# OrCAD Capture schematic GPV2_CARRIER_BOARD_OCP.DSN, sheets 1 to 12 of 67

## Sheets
1 001 Cover Page: title: Glacier Point V2; rev: 3.02
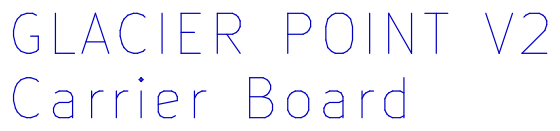
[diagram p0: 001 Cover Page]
2 002 Title Page Index
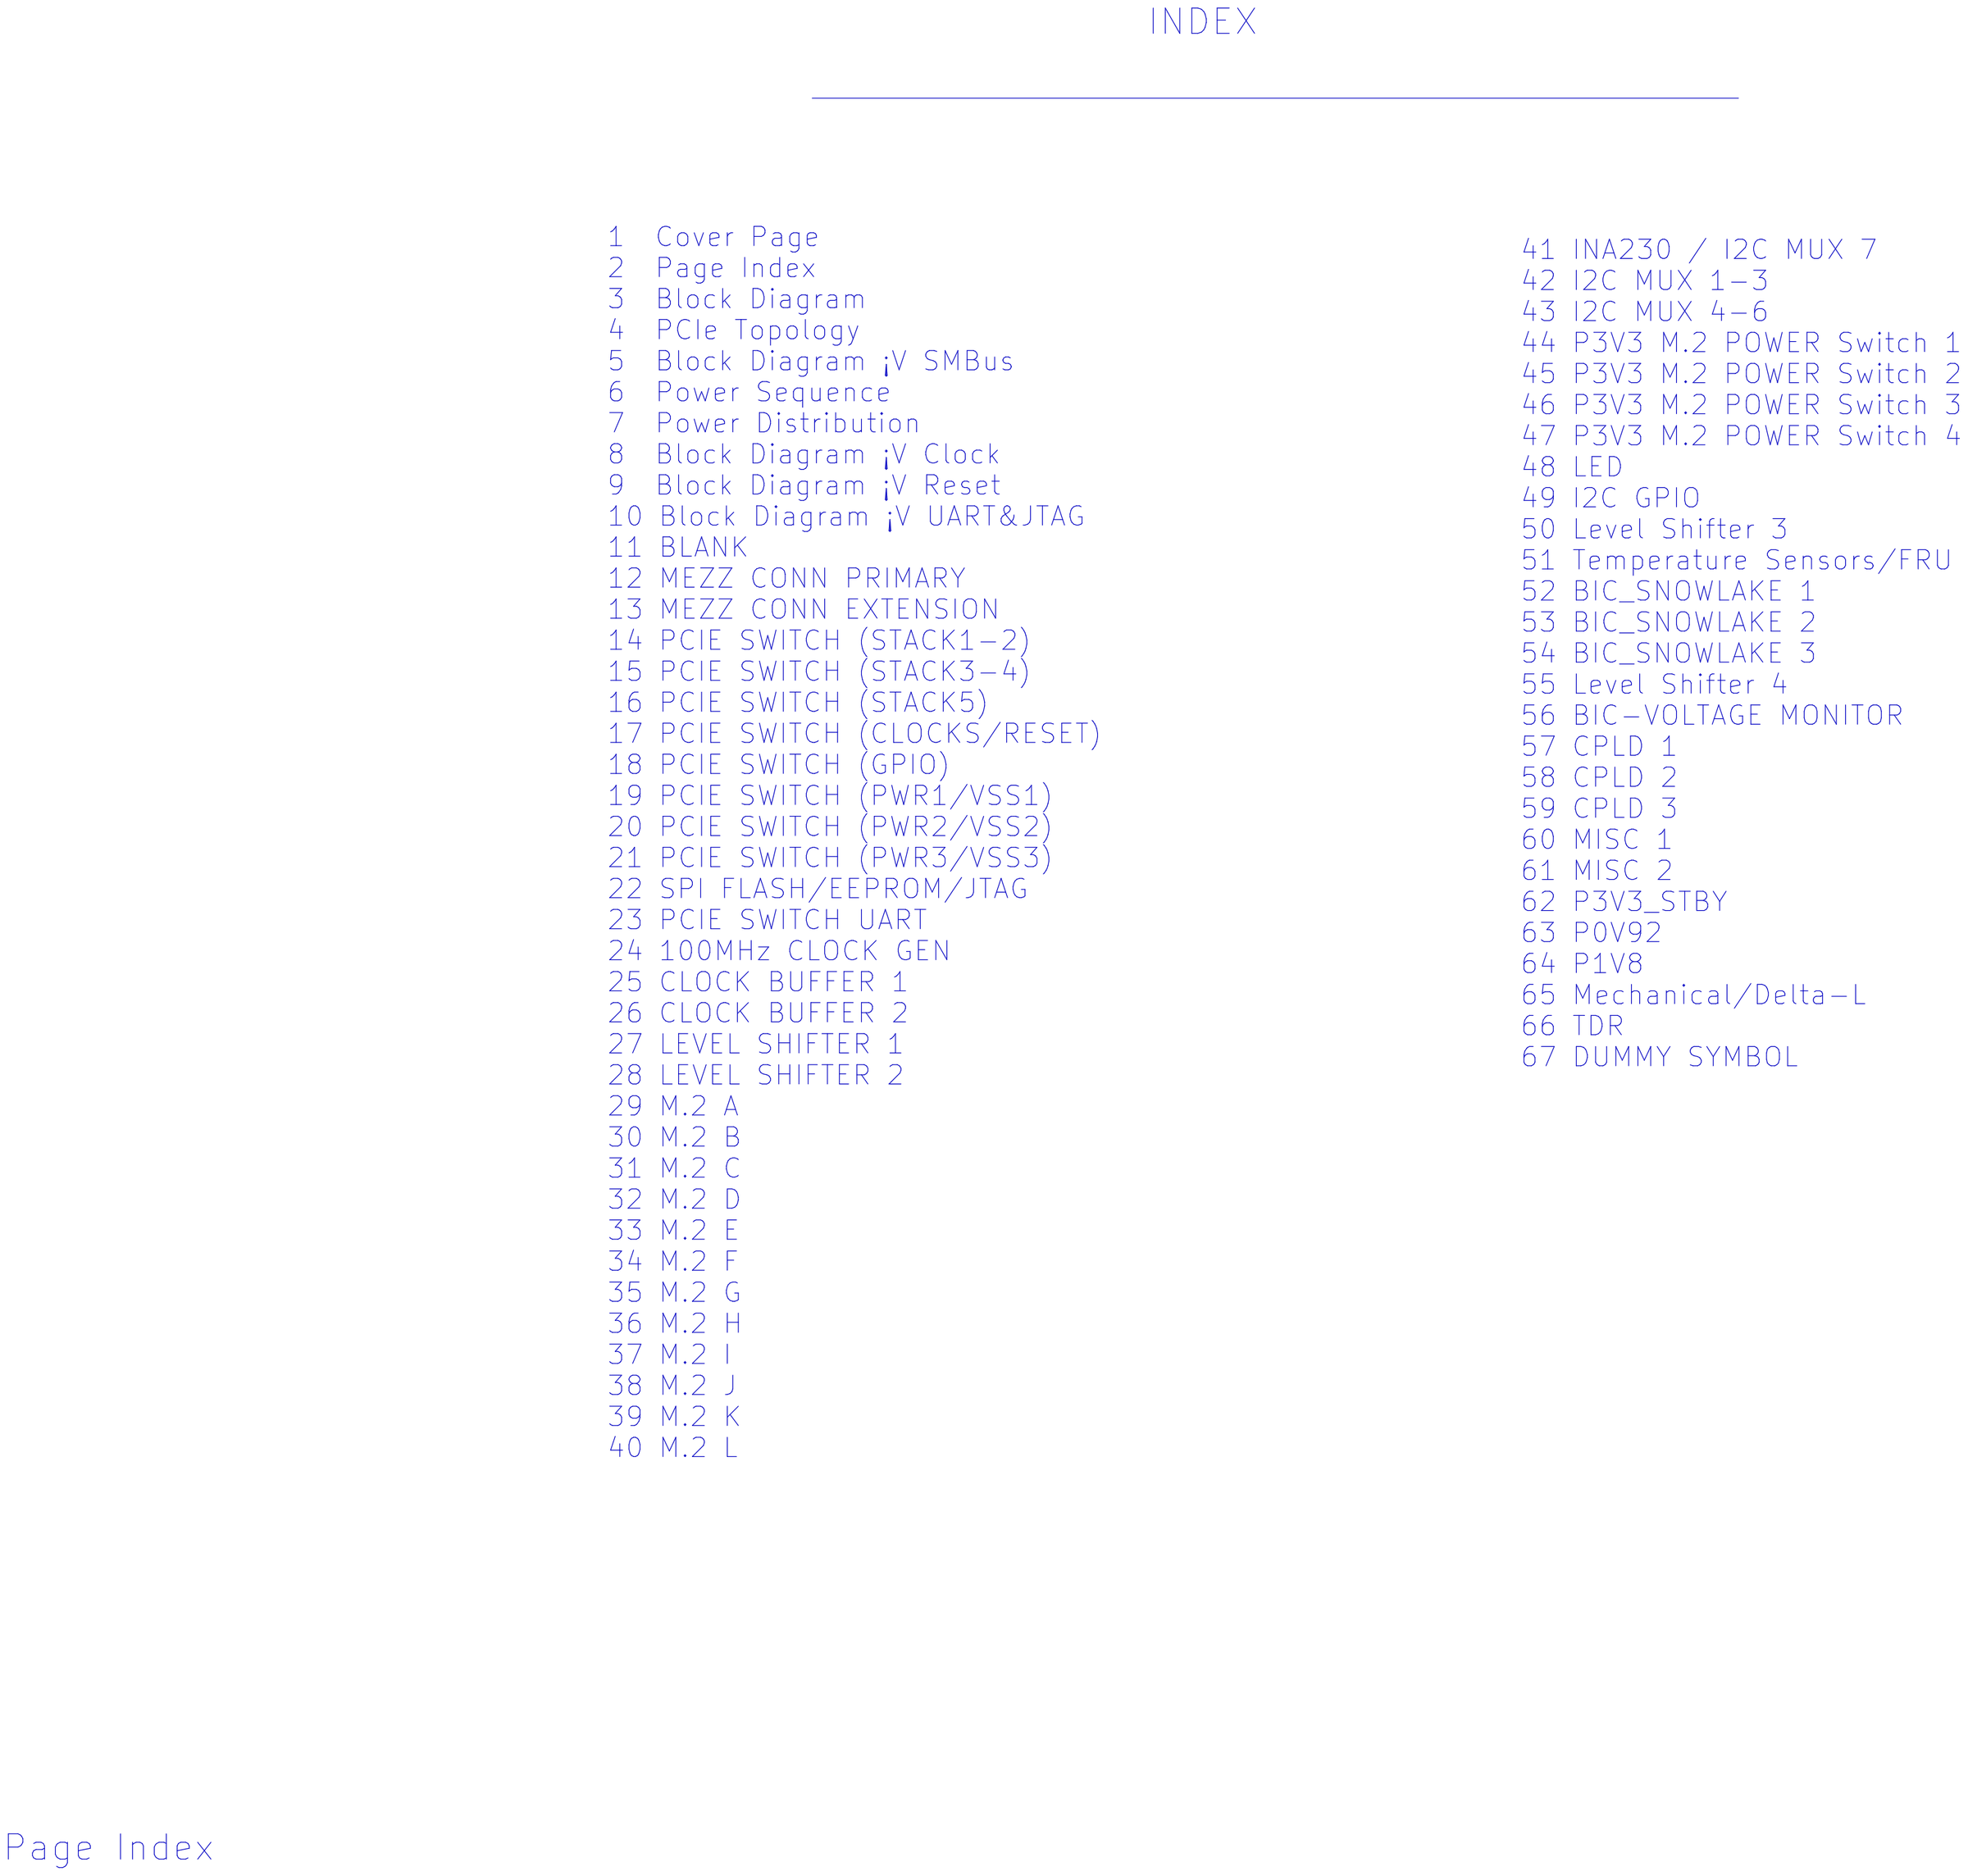
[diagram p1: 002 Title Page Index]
3 003 Block Diagram
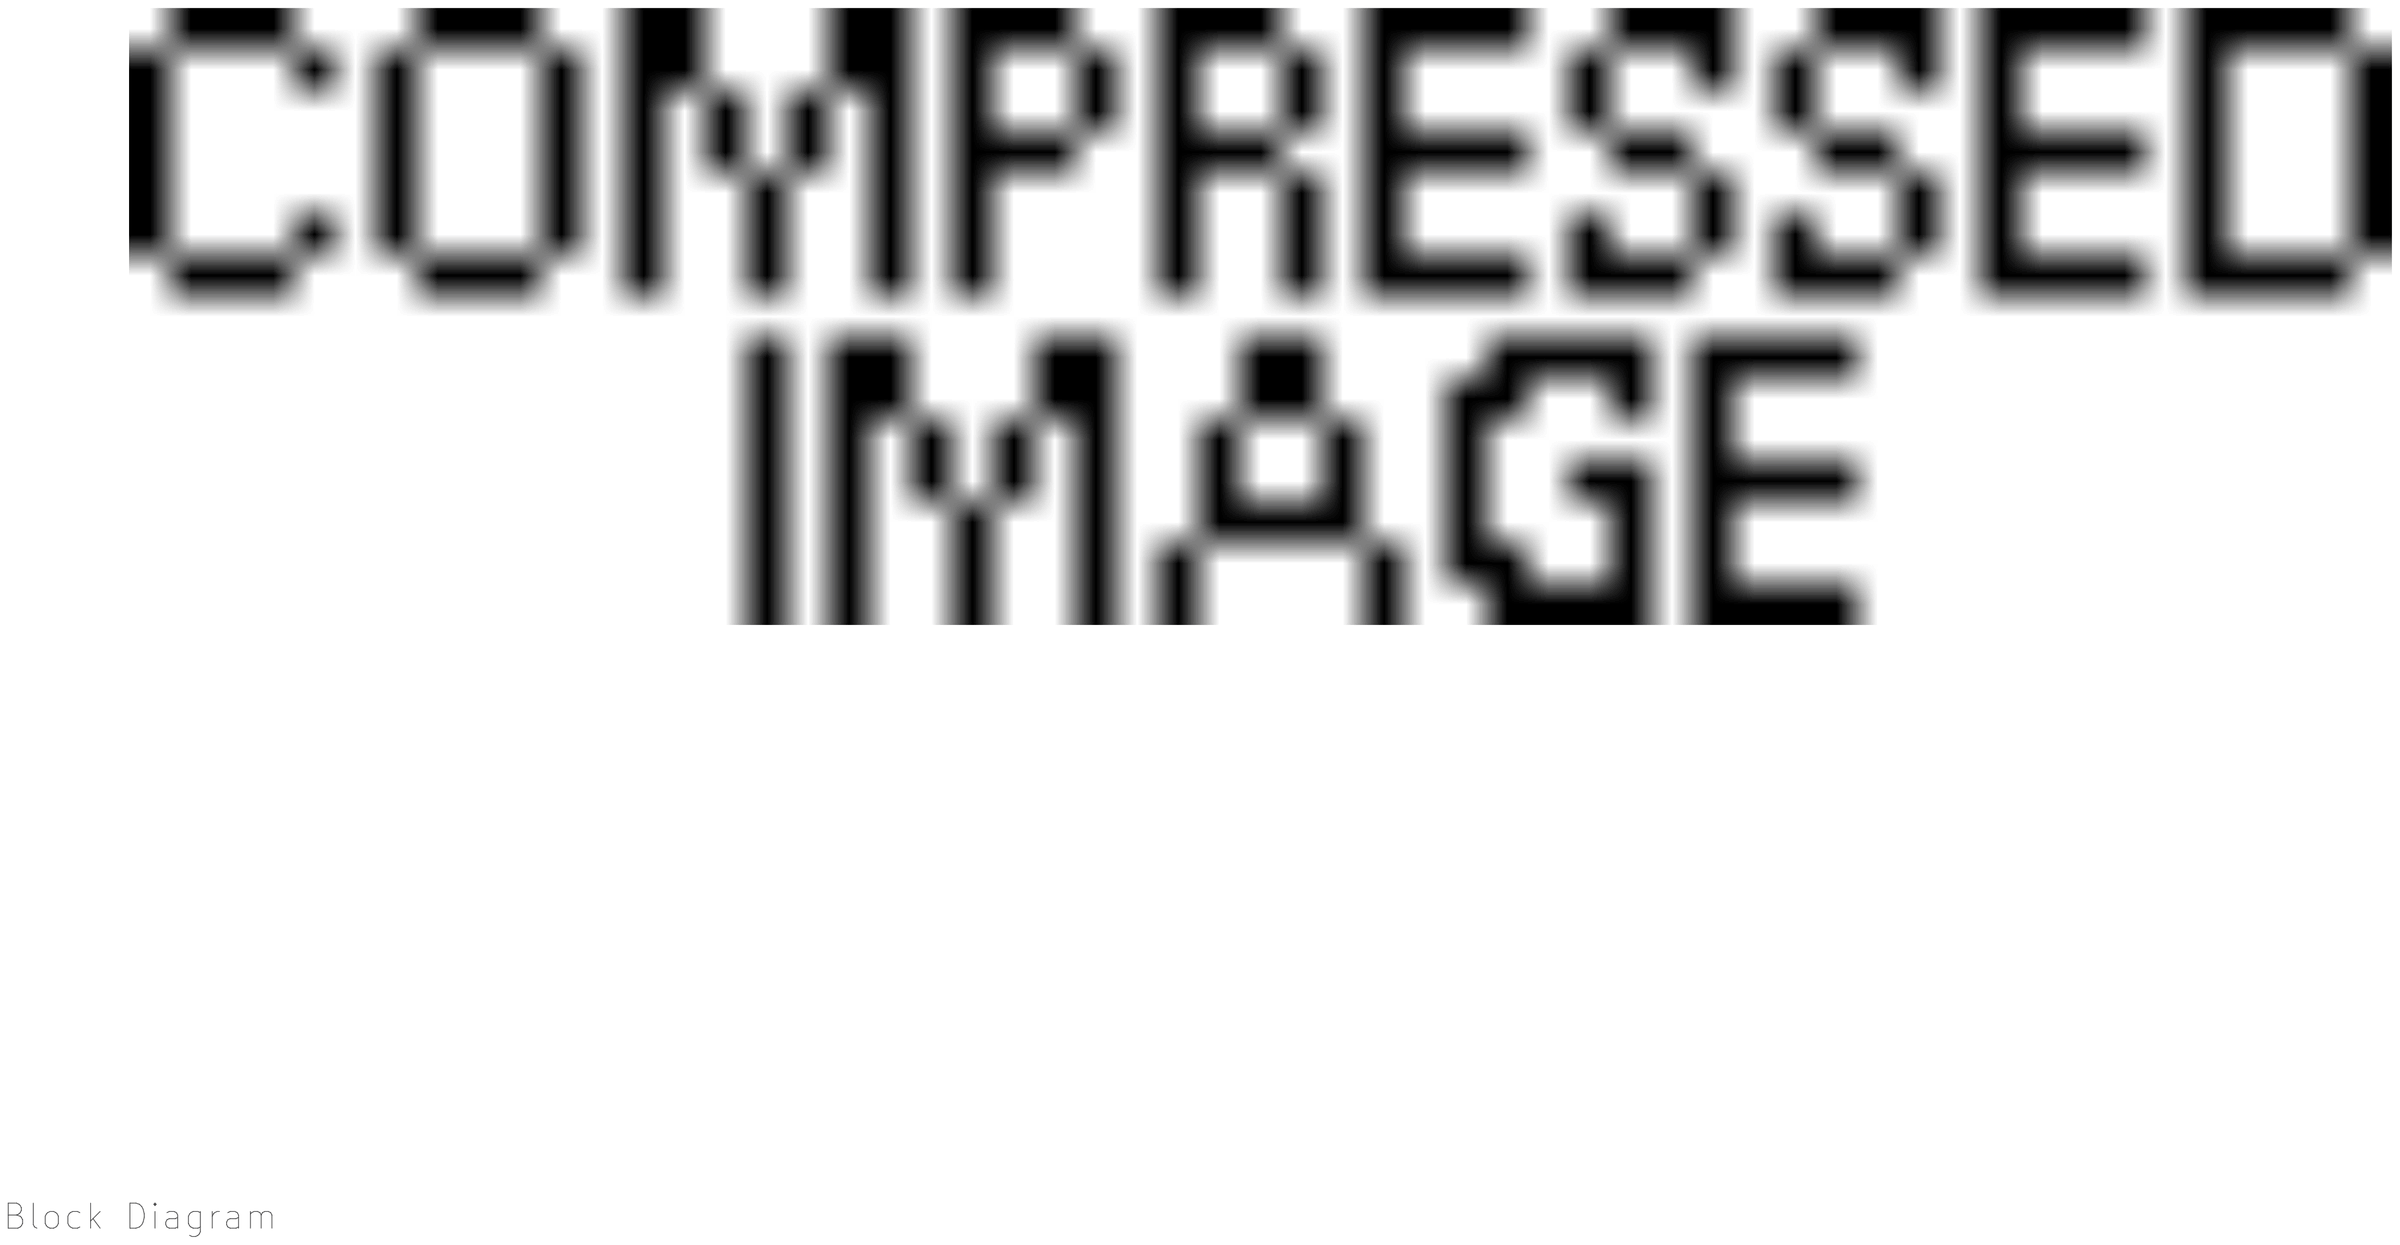
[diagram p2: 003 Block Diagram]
4 004 PCIe Topology
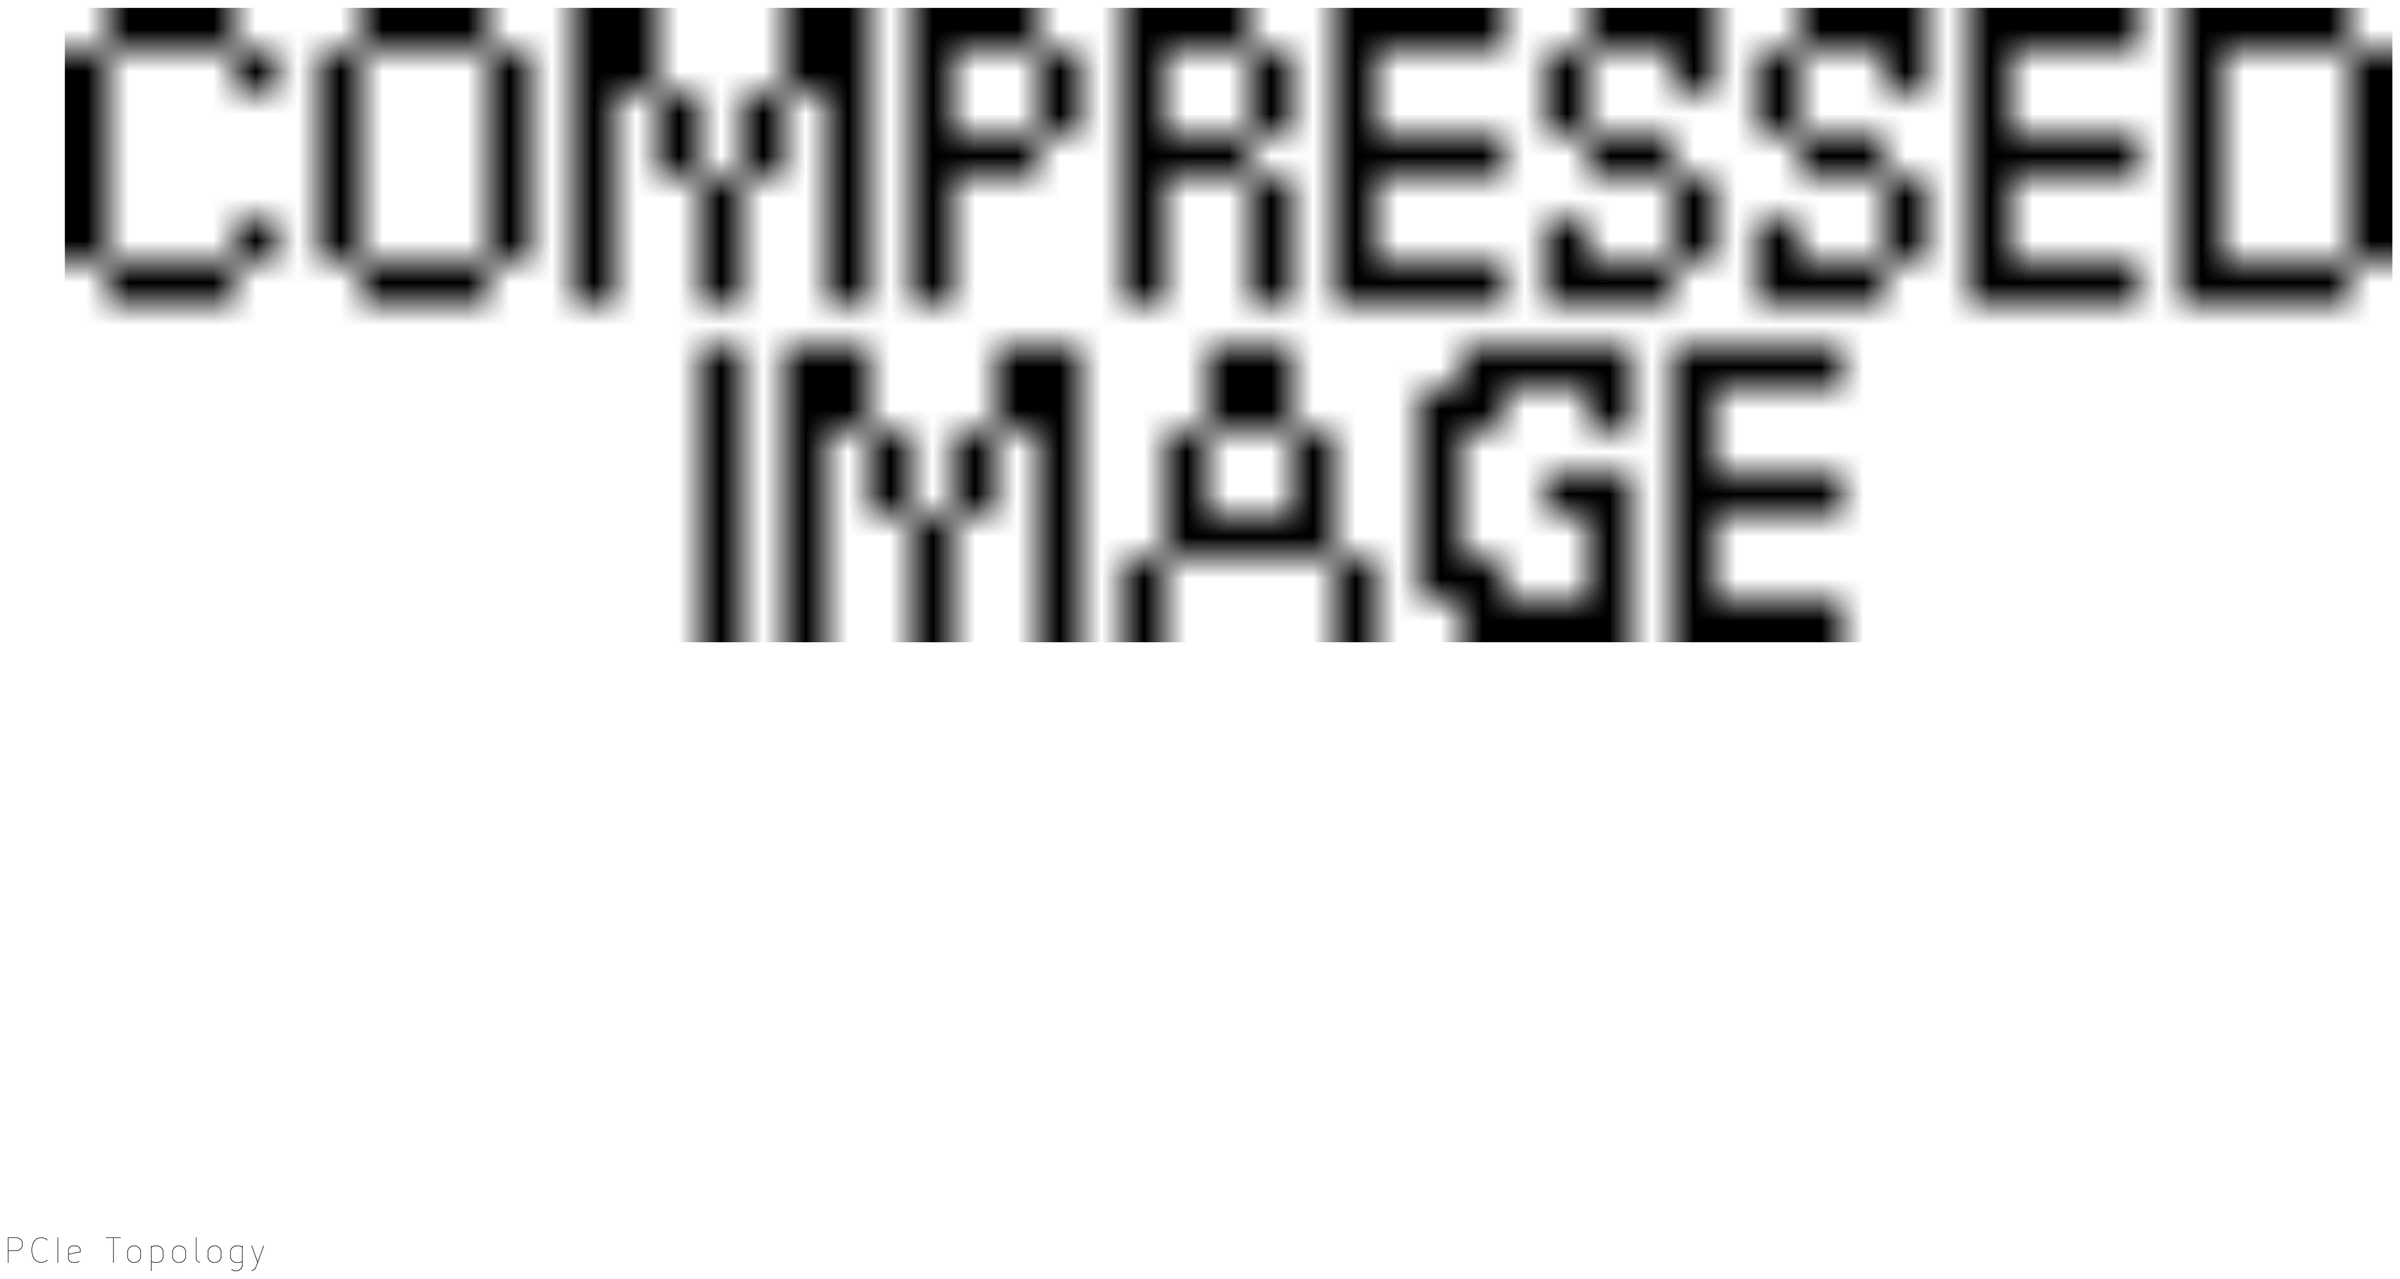
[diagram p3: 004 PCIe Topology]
5 005 Block Diagram - SMBus
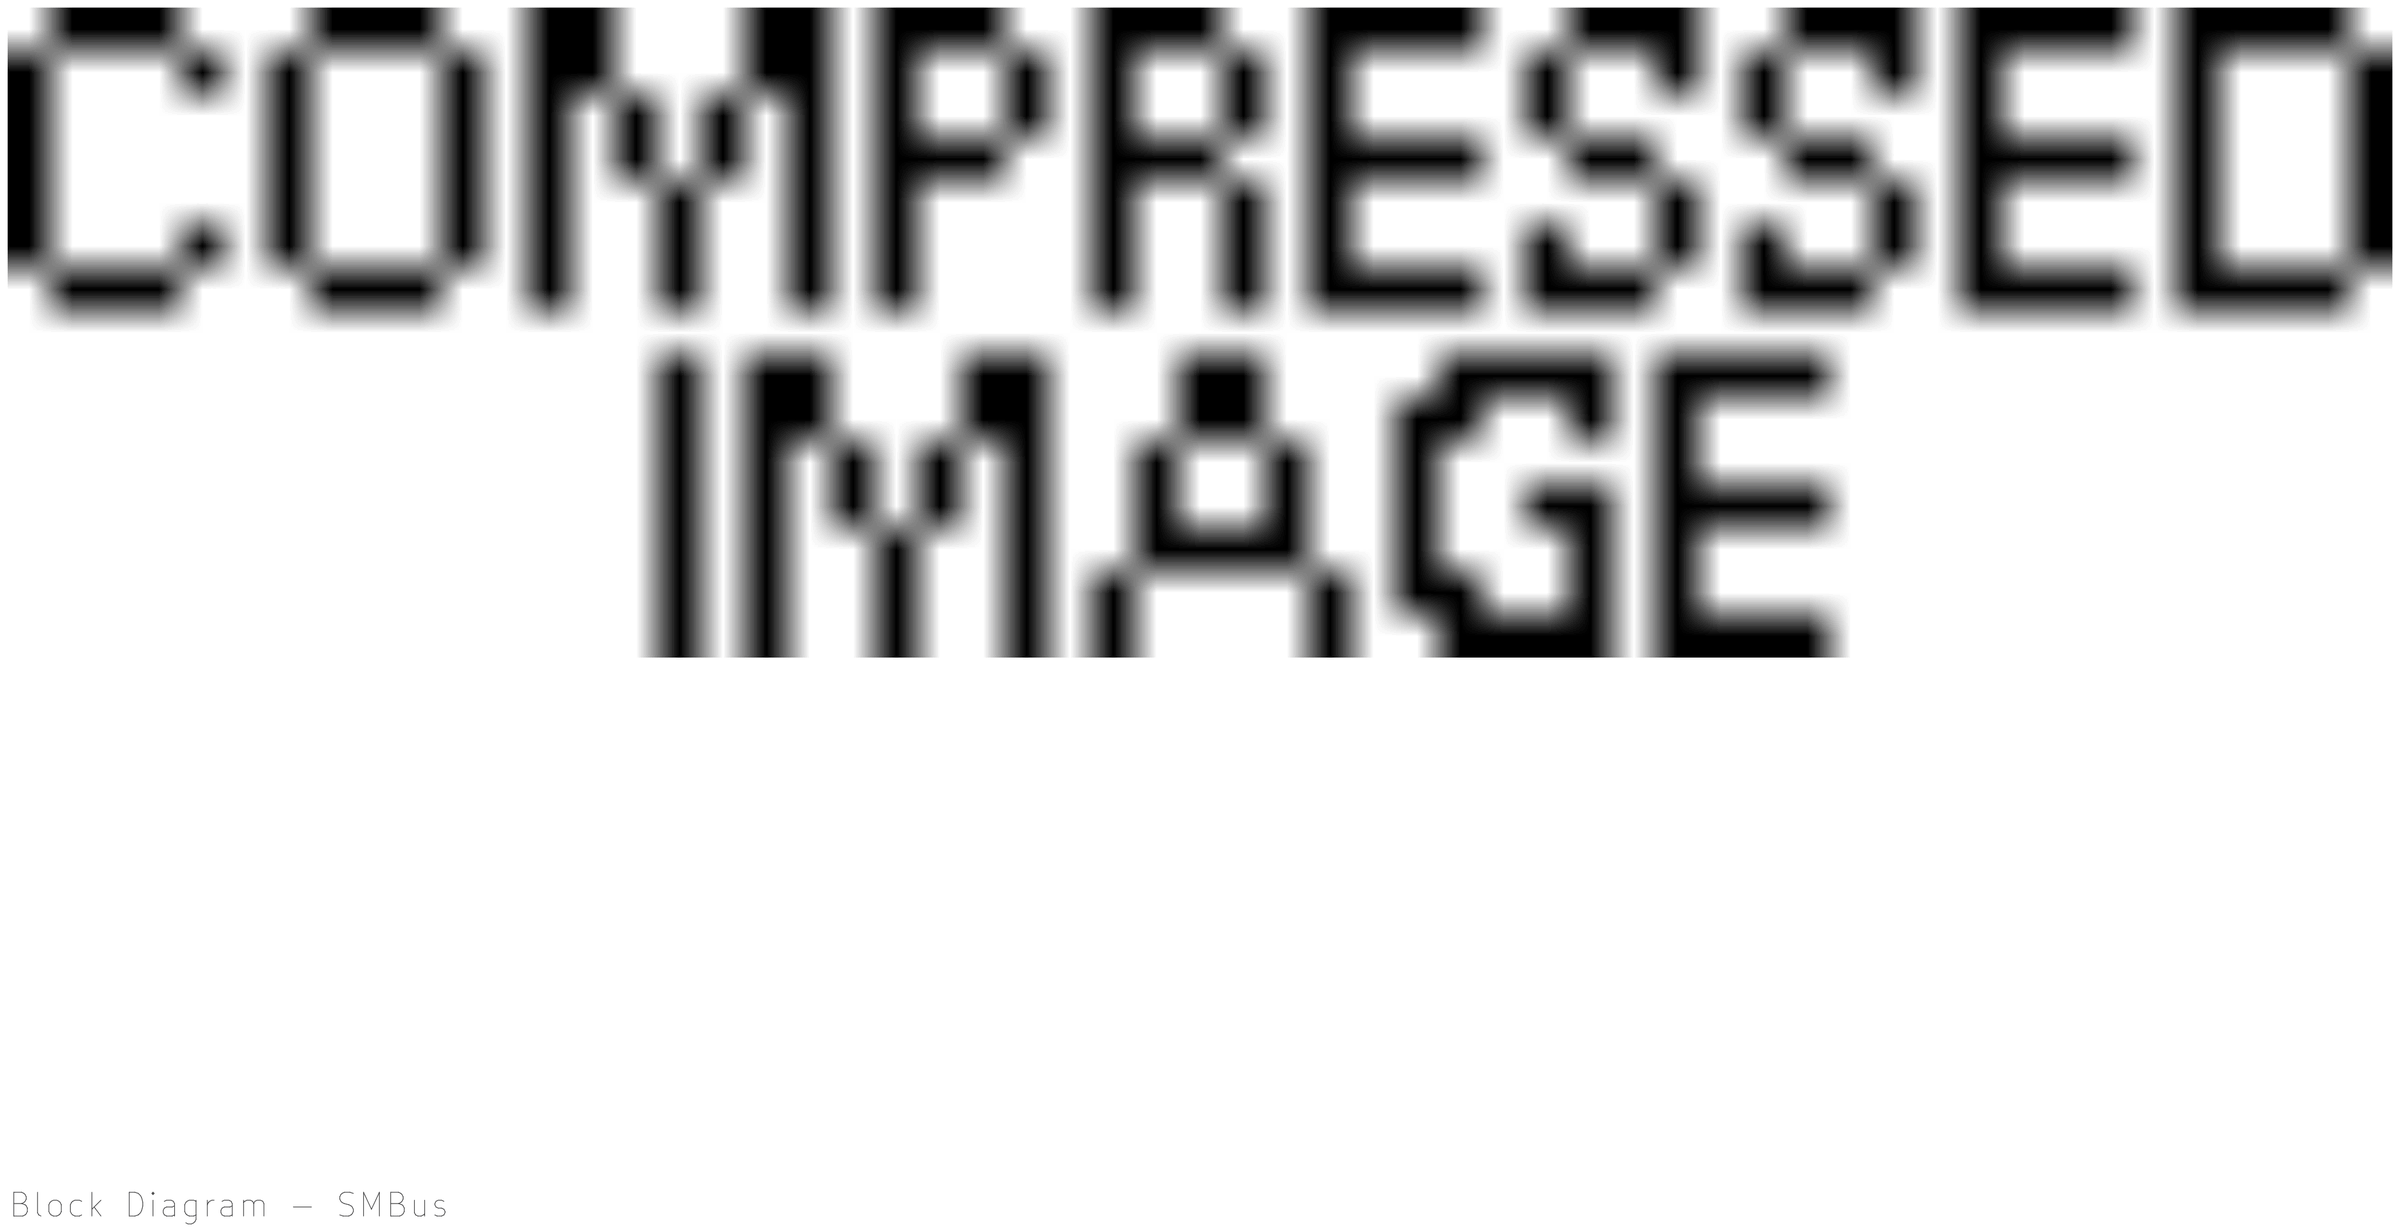
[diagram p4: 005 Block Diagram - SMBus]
6 006 Power Sequence
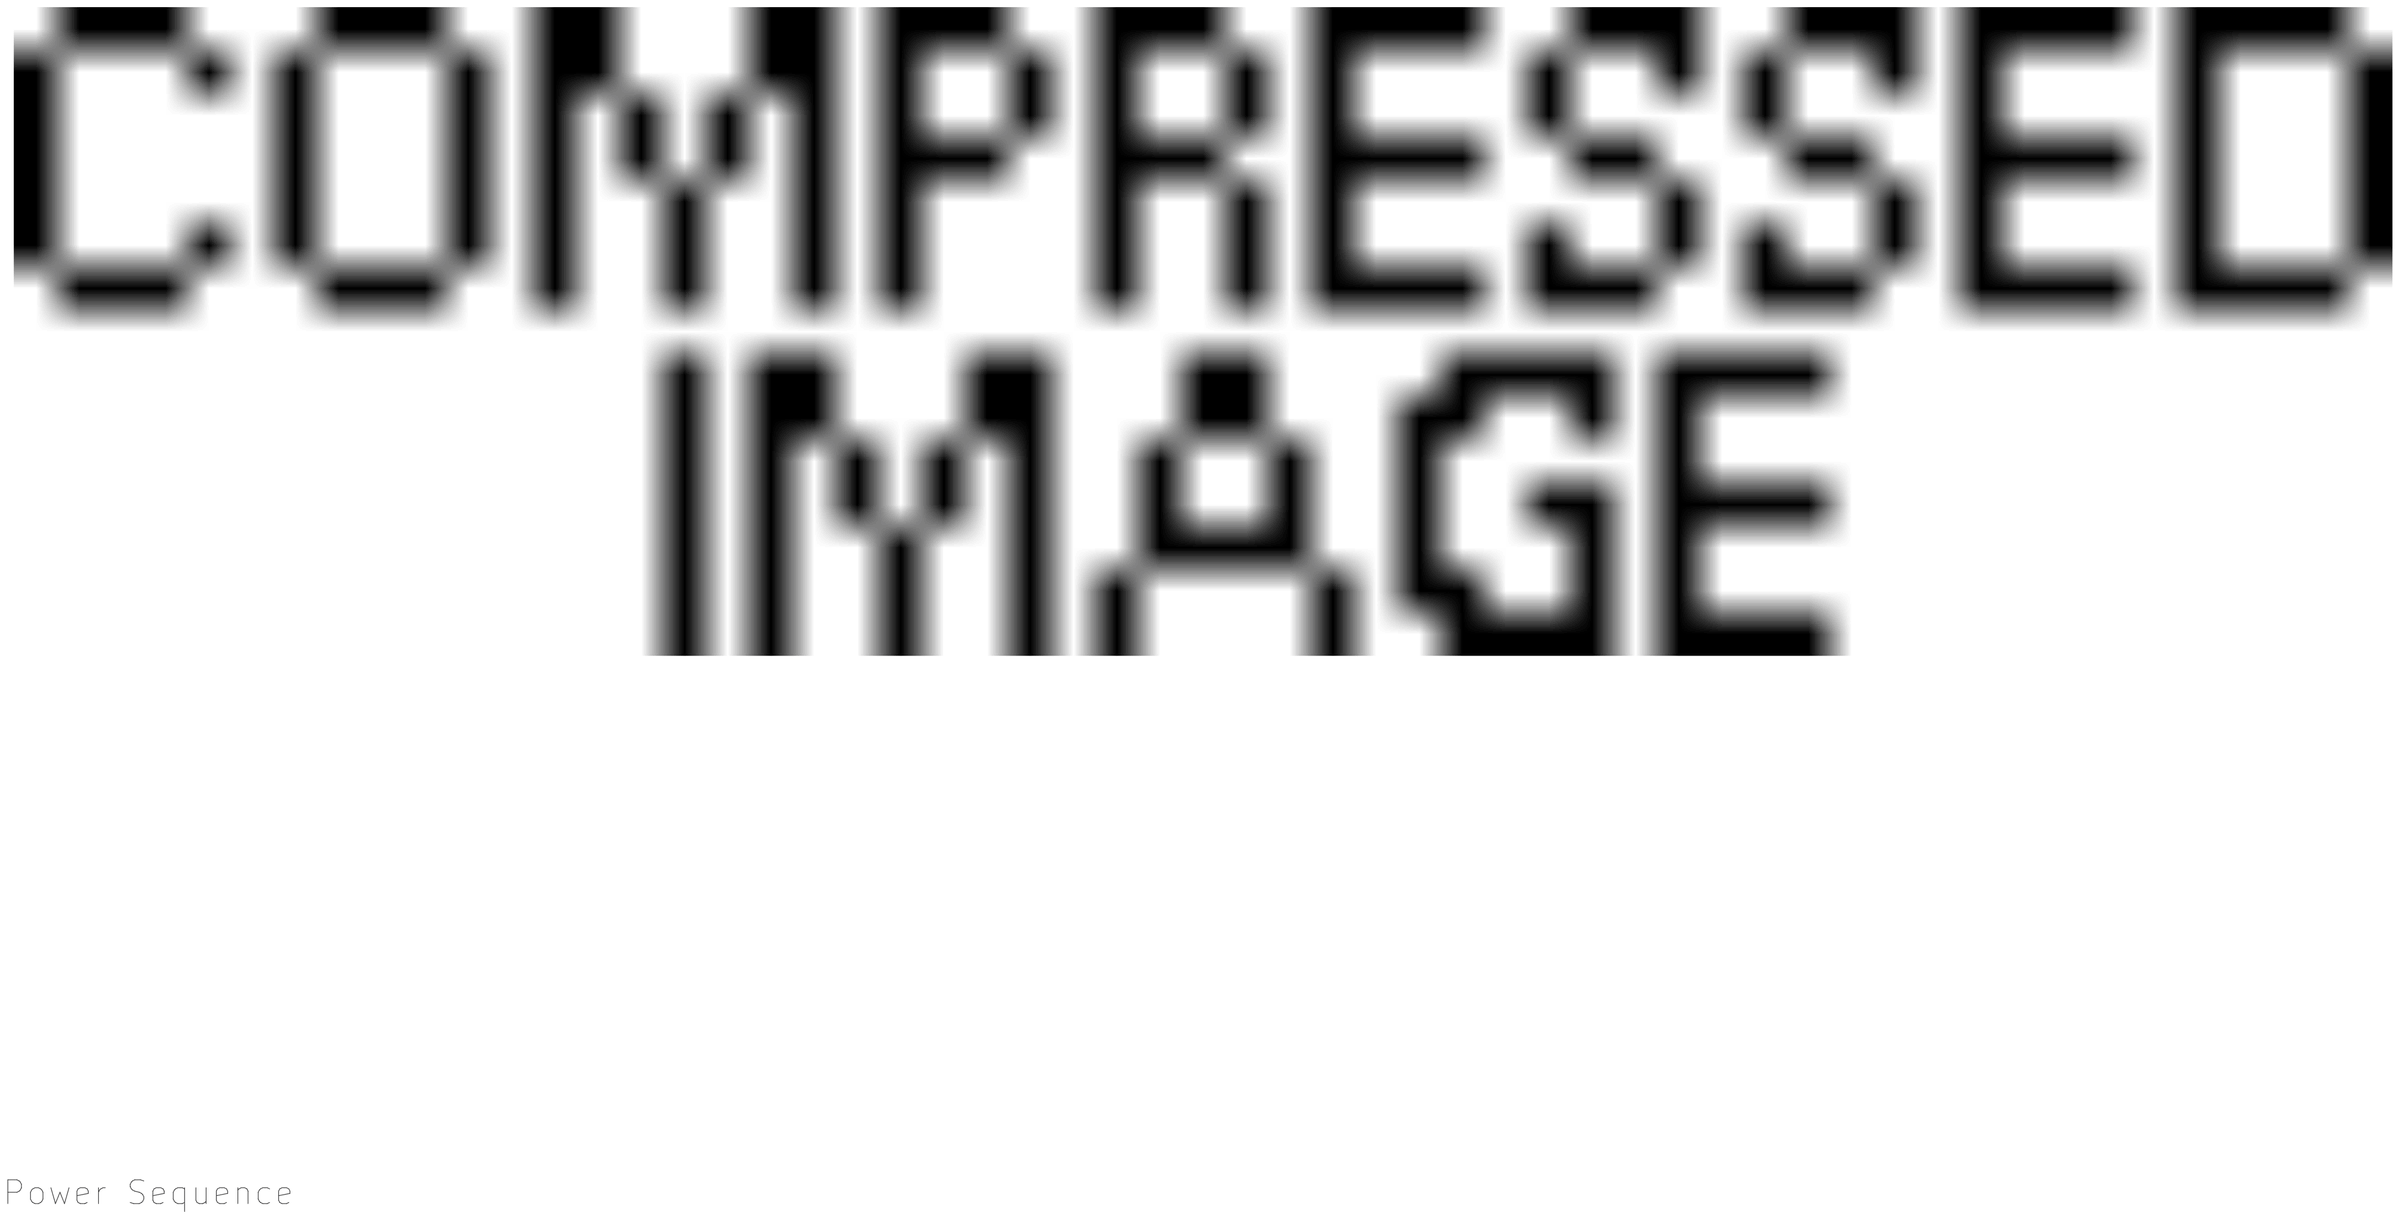
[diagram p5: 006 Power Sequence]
7 007 Power Distribution
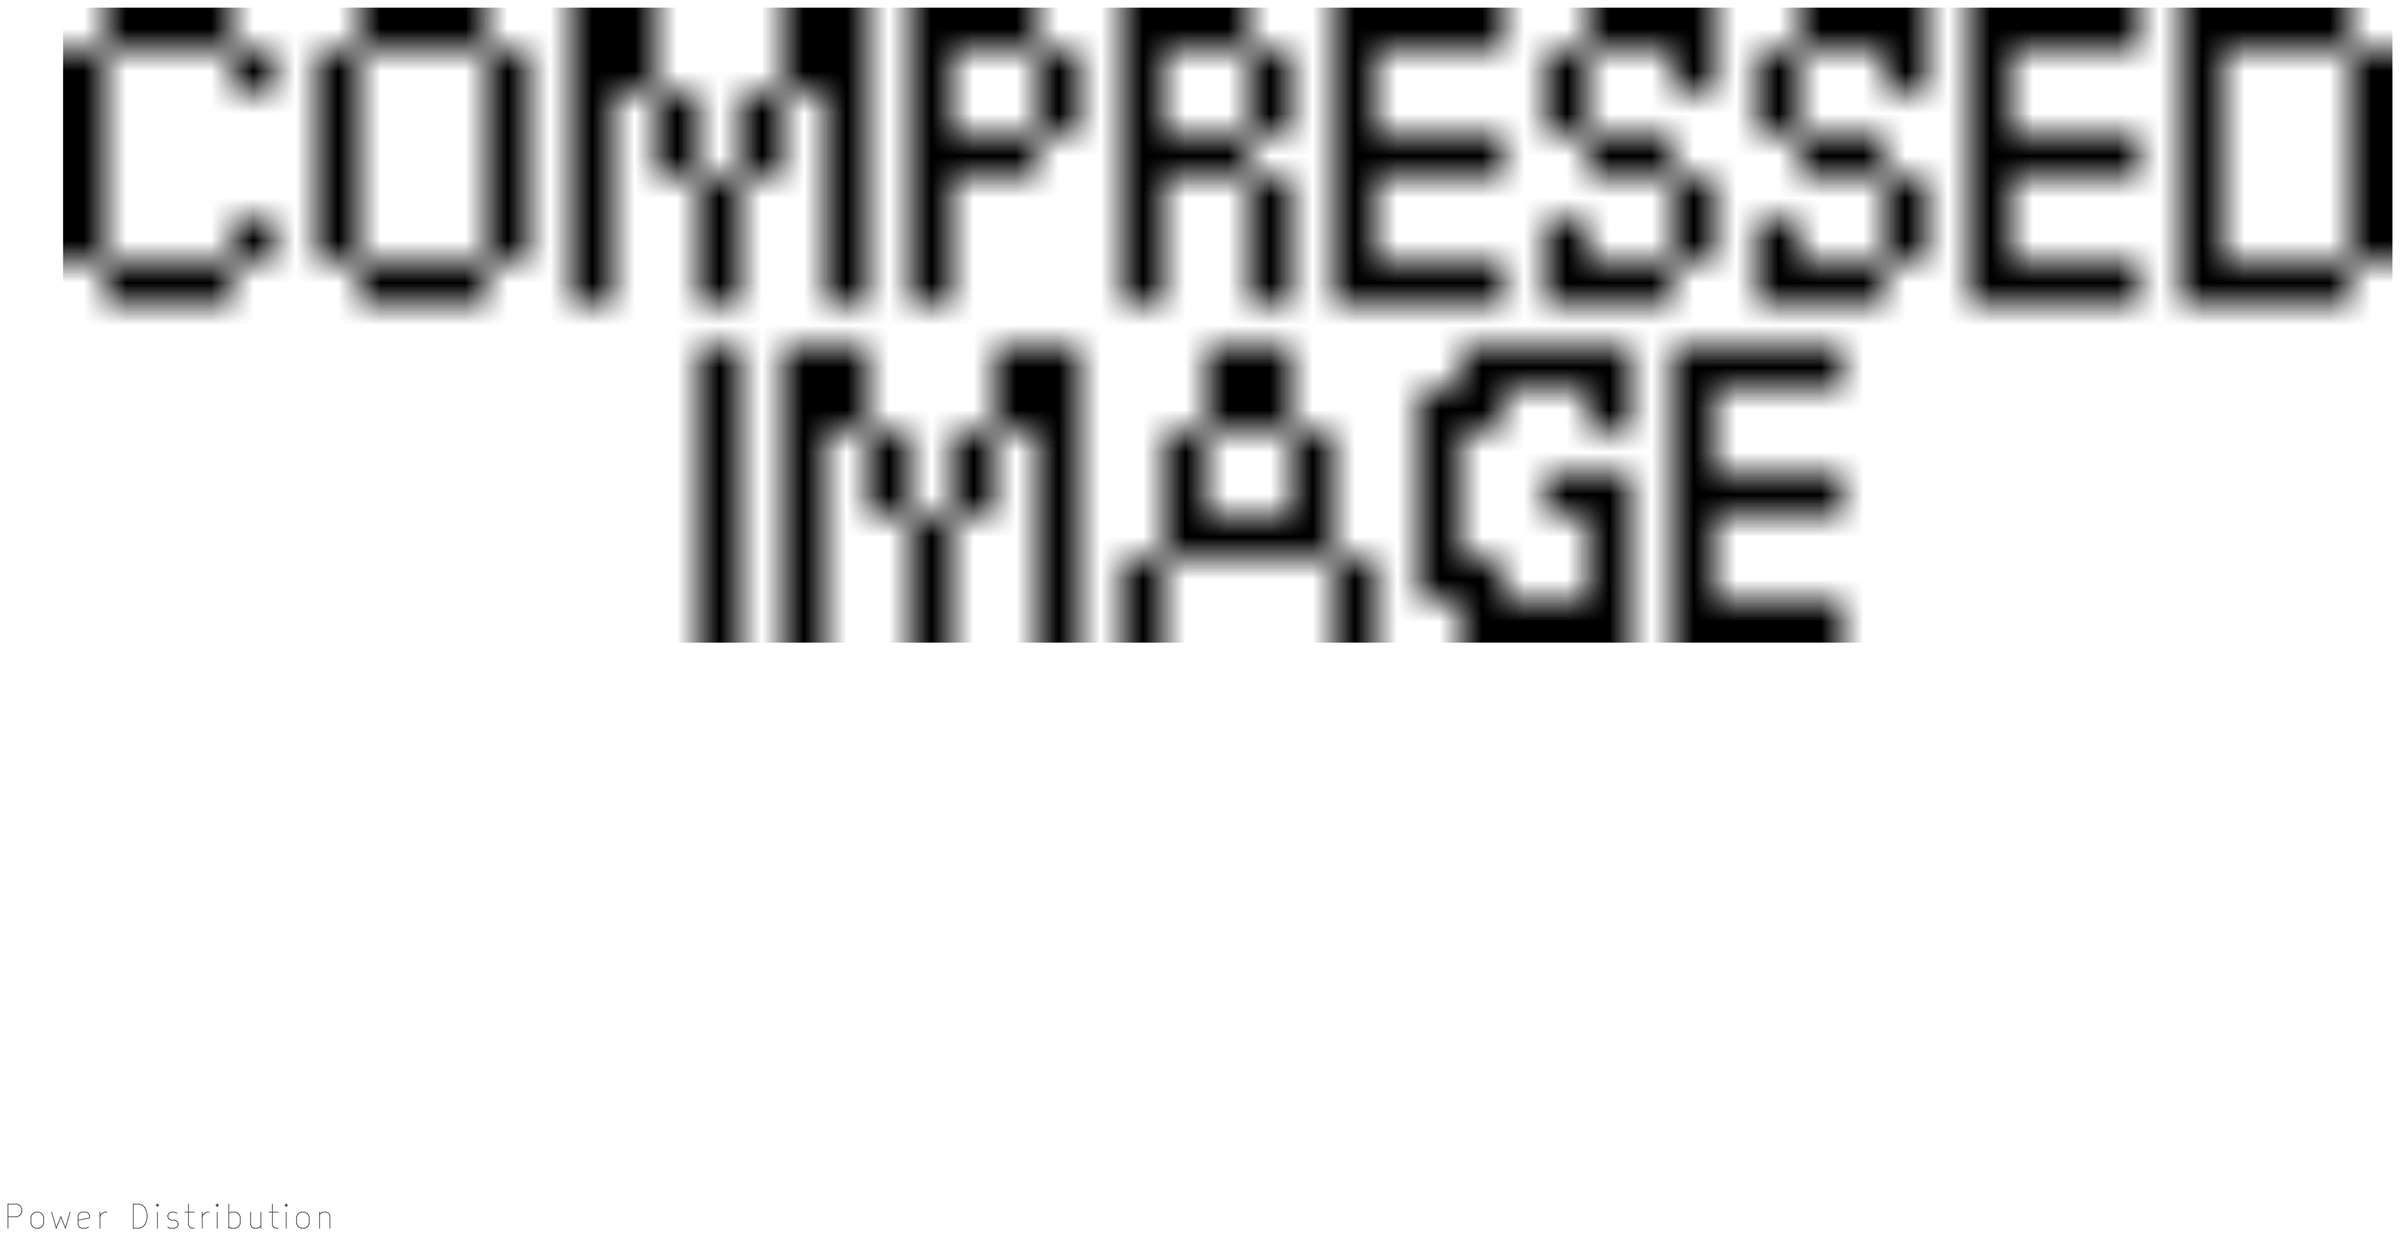
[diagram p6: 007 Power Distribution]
8 008 Block Diagram - Clock
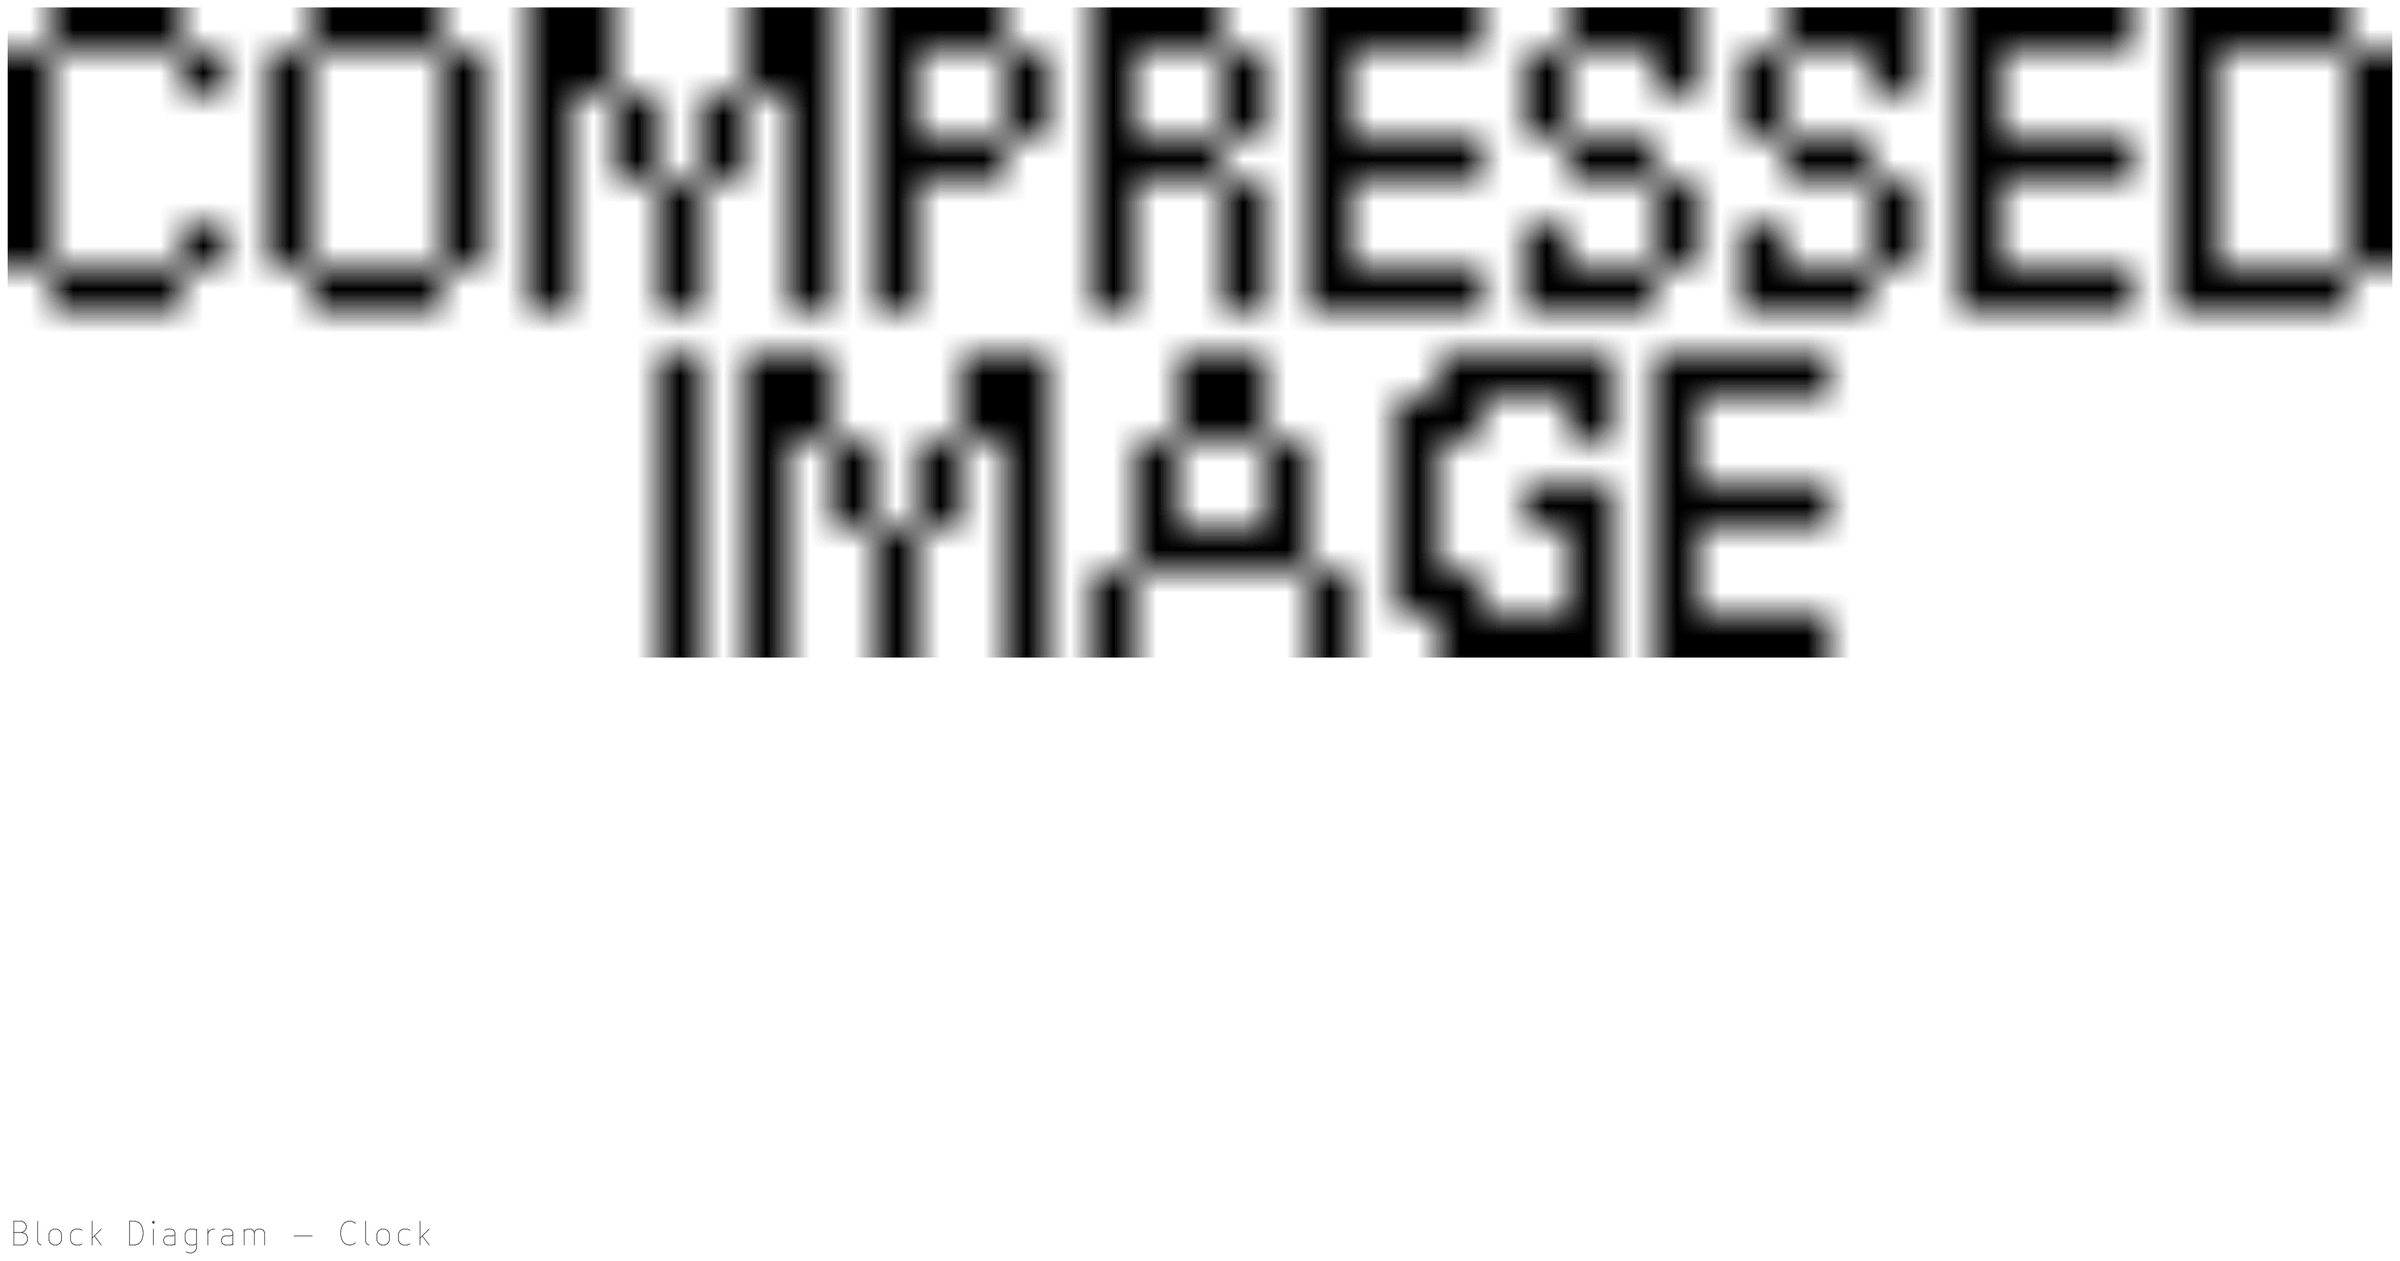
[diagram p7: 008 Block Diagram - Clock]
9 009 Block Diagram - Reset
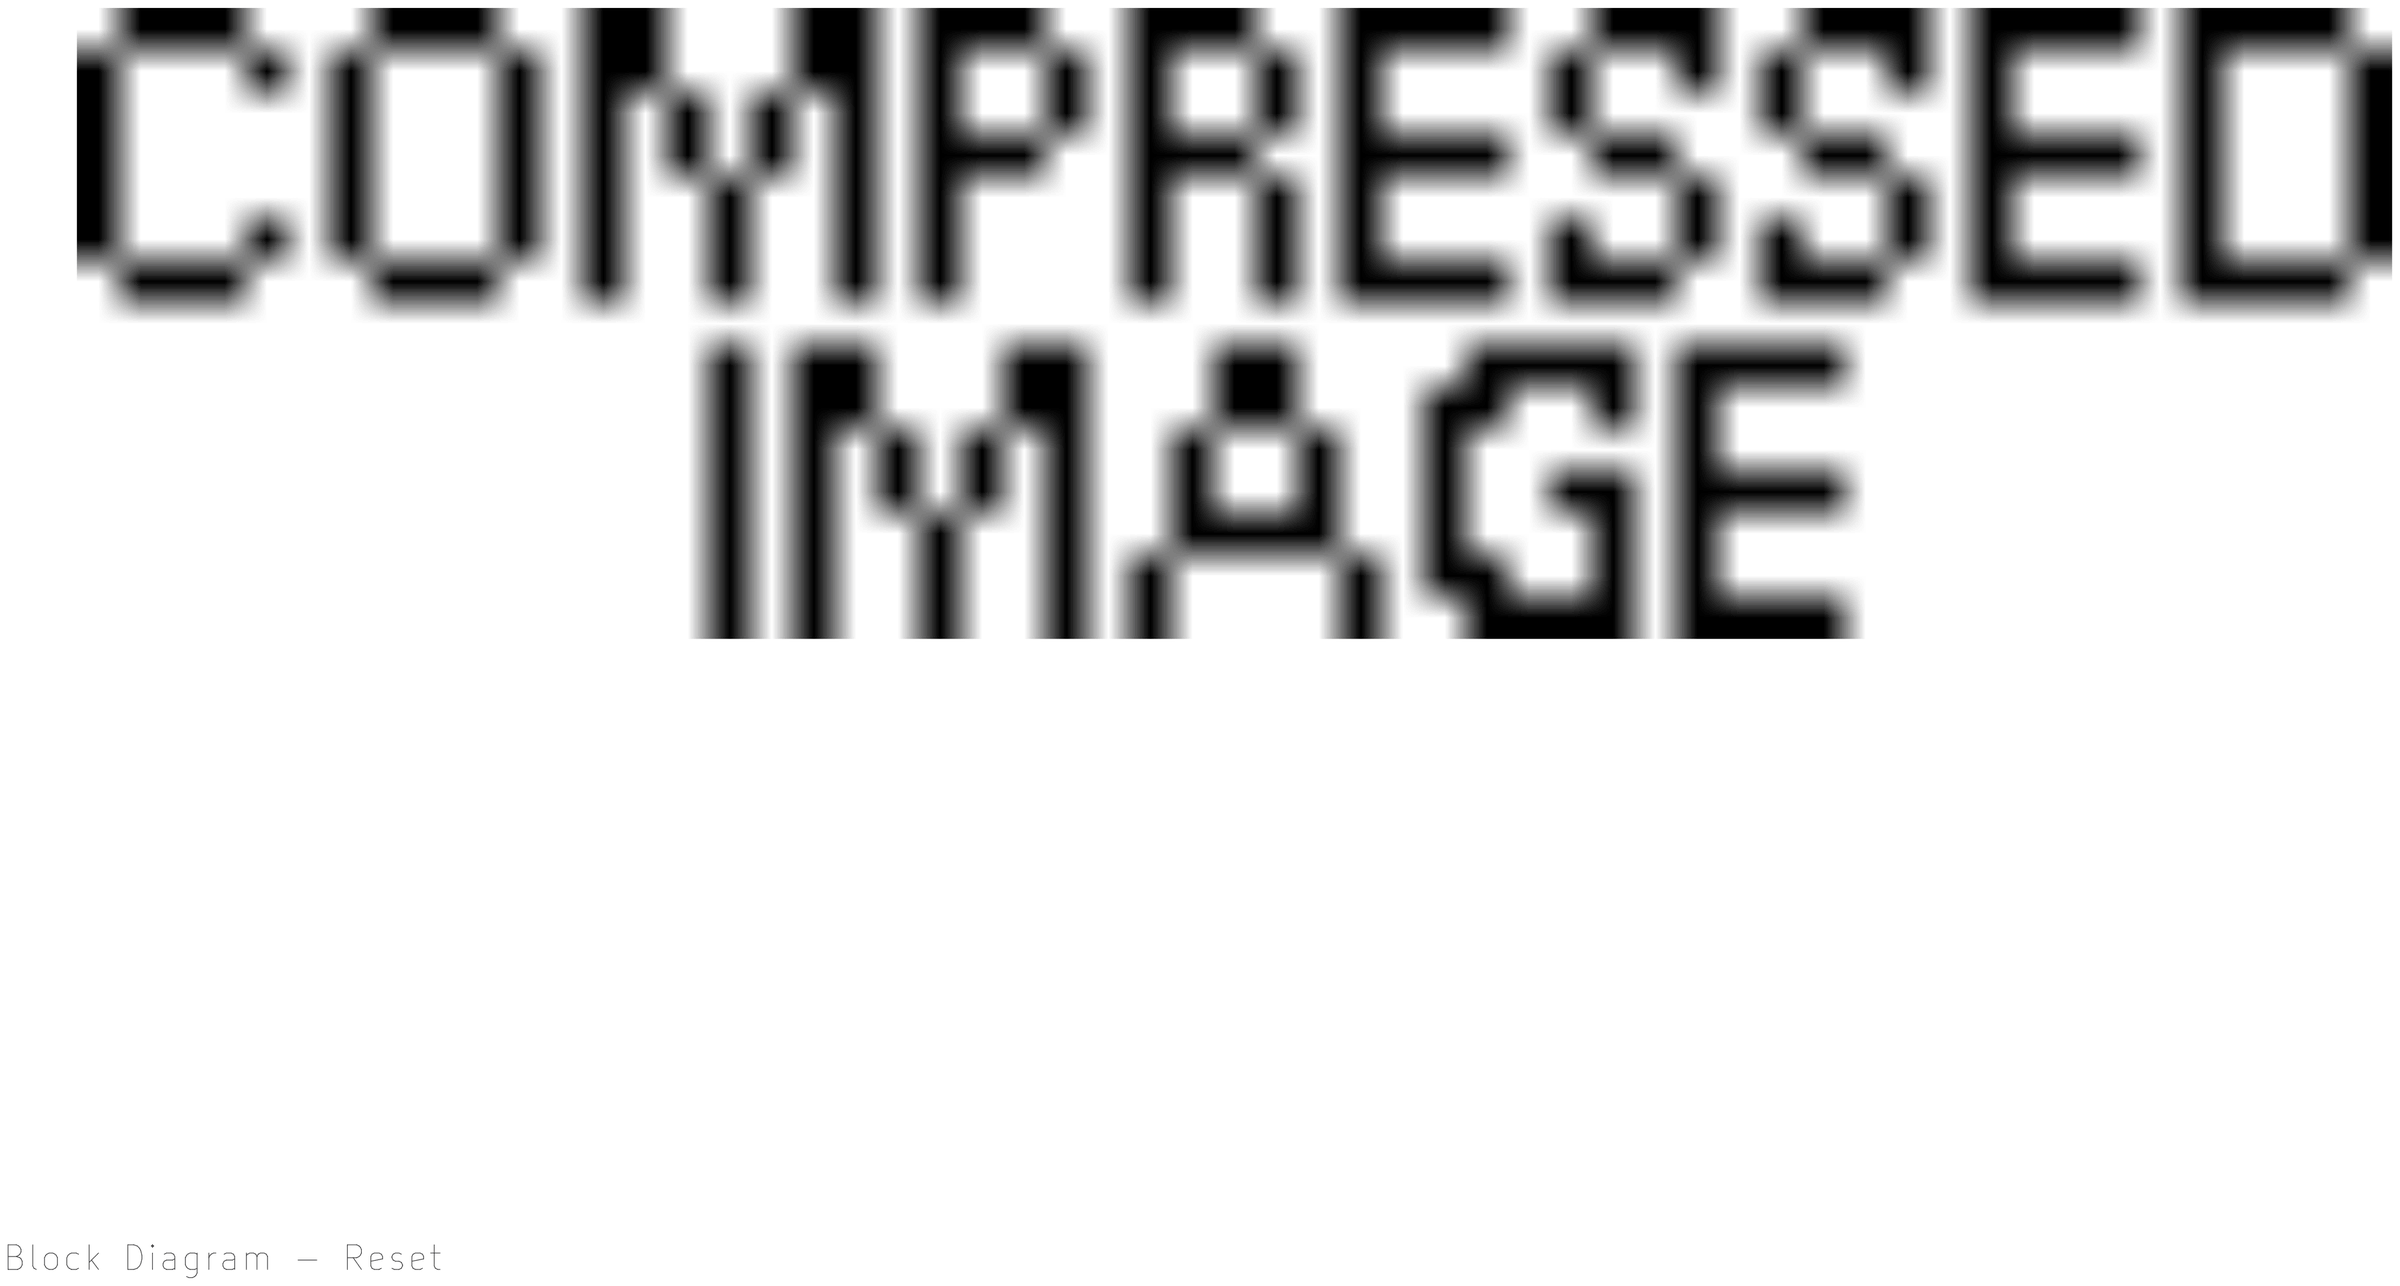
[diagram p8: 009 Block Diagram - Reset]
10 010 Block Diagram - UART&JTAG
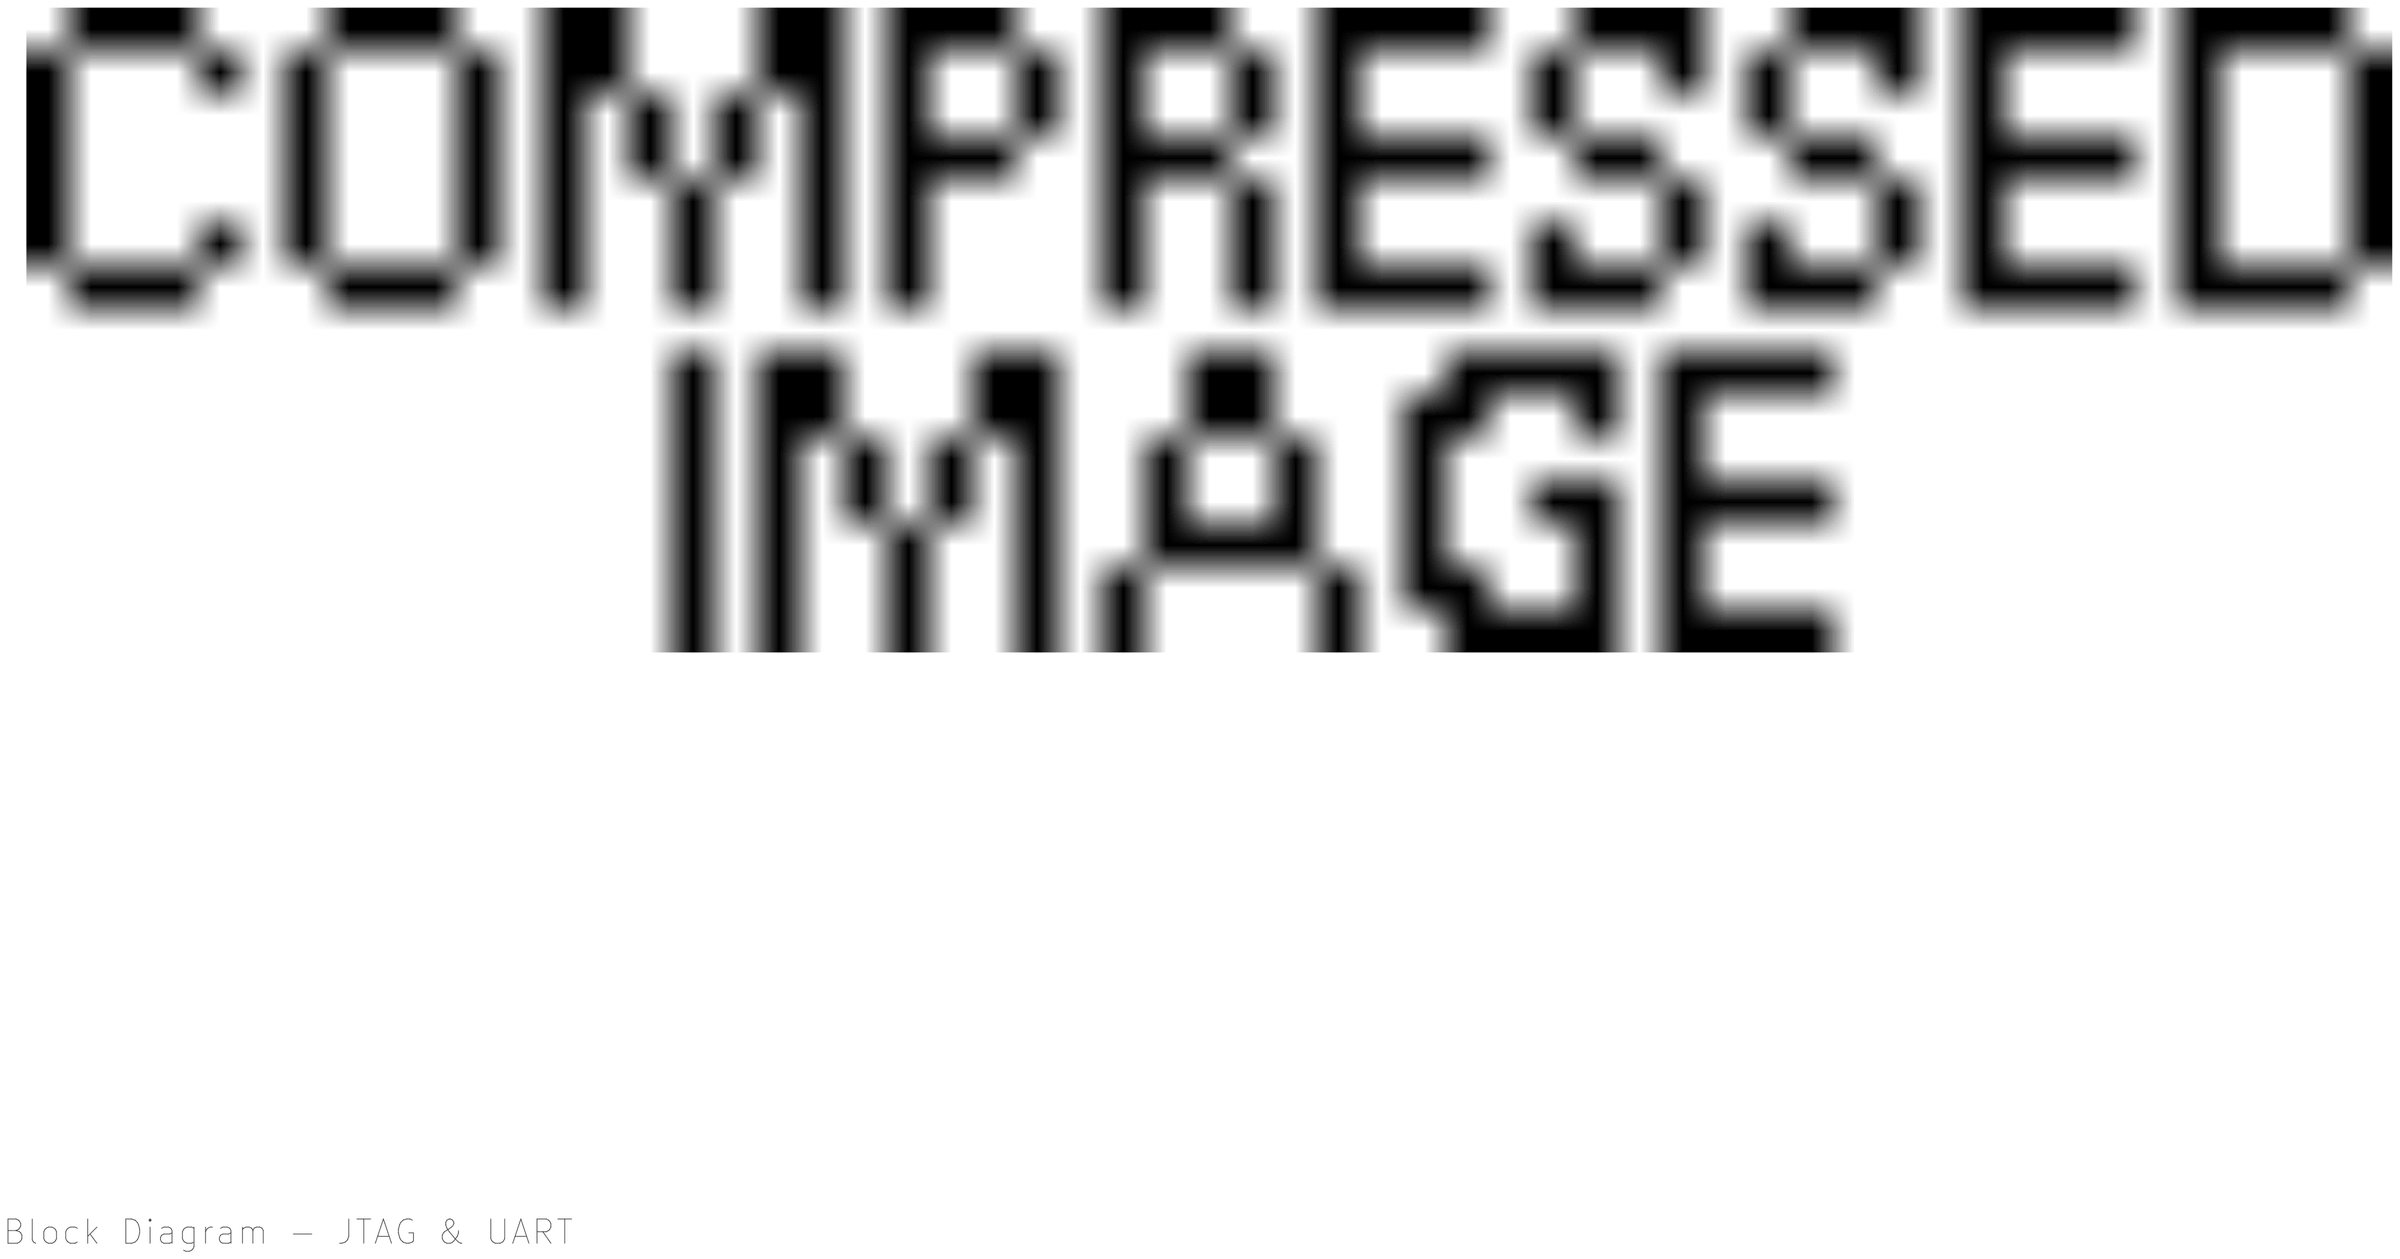
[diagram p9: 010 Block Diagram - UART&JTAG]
11 011 BLANK
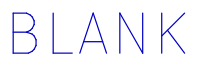
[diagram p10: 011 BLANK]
12 012 MEZZ CONN PRIMARY: size C
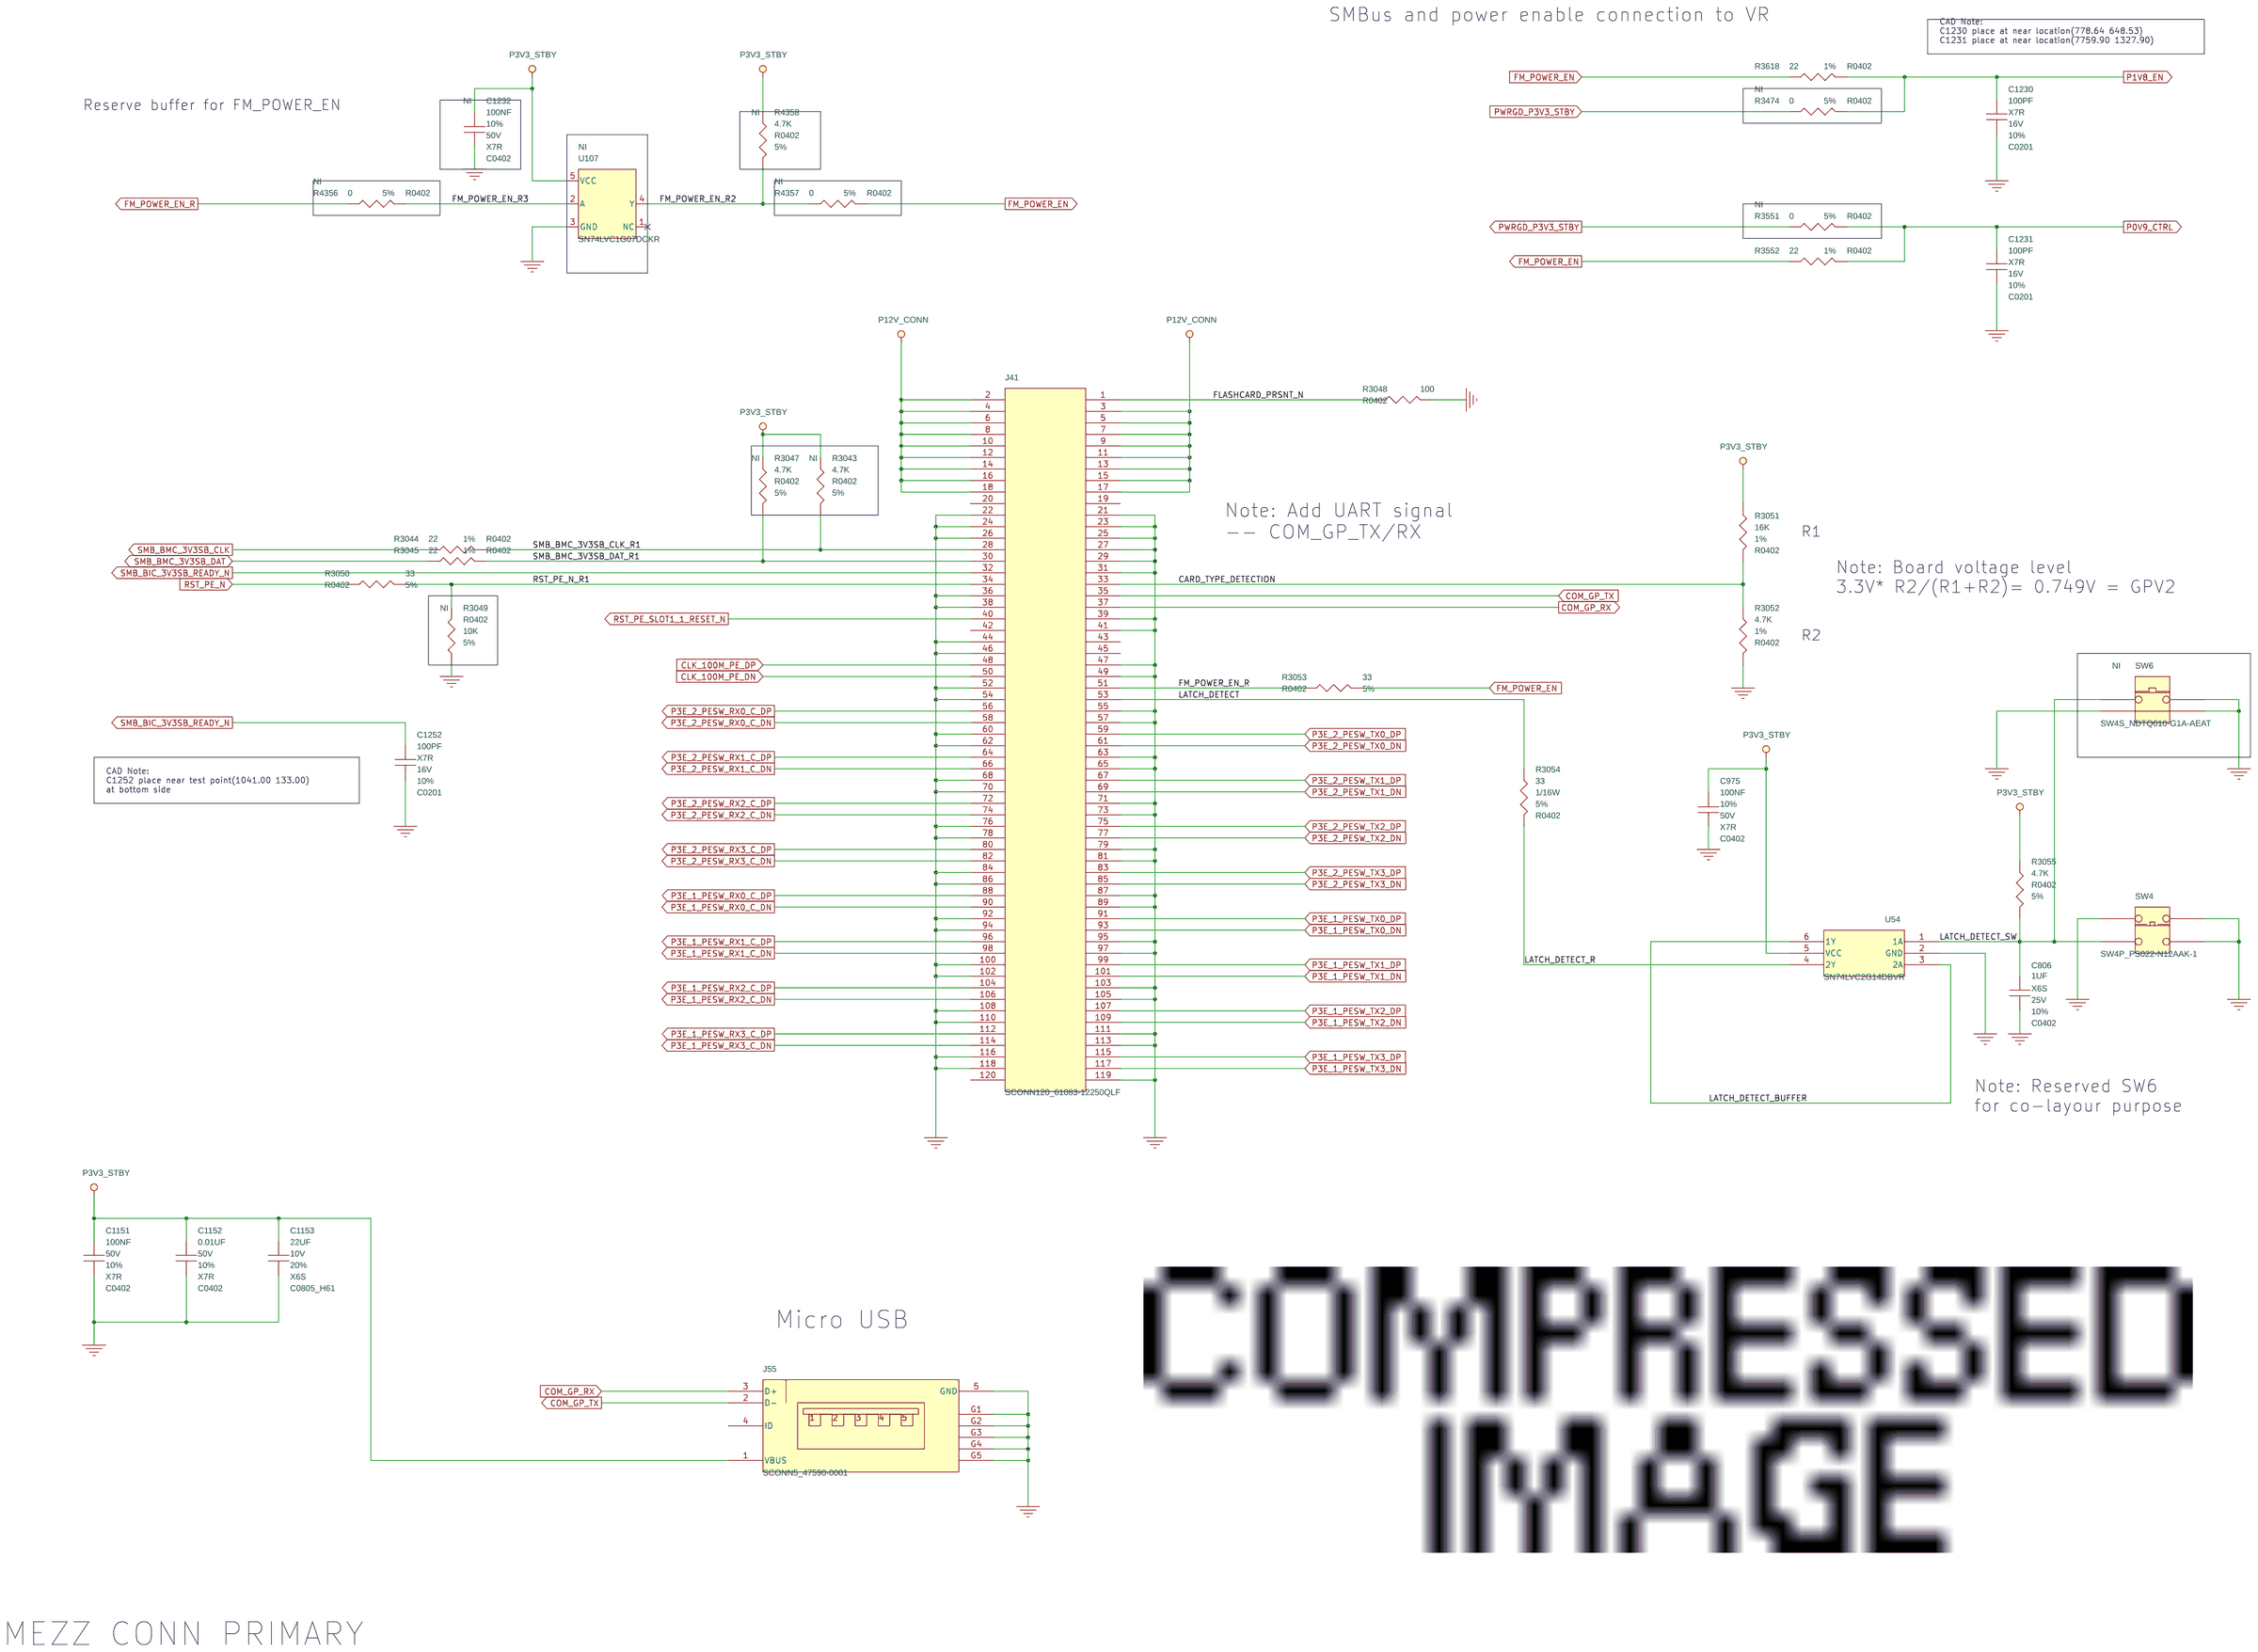
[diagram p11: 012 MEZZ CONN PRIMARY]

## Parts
C806  1UF  [C0402]
C975  100NF  [C0402]
C1151  100NF  [C0402]
C1152  0.01UF  [C0402]
C1153  22UF  [C0805_H61]
C1230  100PF  [C0201]
C1231  100PF  [C0201]
C1232  100NF  [C0402]
C1252  100PF  [C0201]
J41  SCONN120_61083-12250QLF  [CON_120S2H2D_P0-8W4-4_LUV_H237]
J55  SCONN5_47590-0001  [USB1XBD]
R3043  4.7K  [R0402]
R3044  22  [R0402]
R3045  22  [R0402]
R3047  4.7K  [R0402]
R3048  100  [R0402]
R3049  10K  [R0402]
R3050  33  [R0402]
R3051  16K  [R0402]
R3052  4.7K  [R0402]
R3053  33  [R0402]
R3054  33  [R0402]
R3055  4.7K  [R0402]
R3474  0  [R0402]
R3551  0  [R0402]
R3552  22  [R0402]
R3618  22  [R0402]
R4356  0  [R0402]
R4357  0  [R0402]
R4358  4.7K  [R0402]
SW4  SW4P_PS022-N12AAK-1  [SW4P_PS022-N12AAK-1]
SW6  SW4S_NDTQ010-G1A-AEAT  [SW4S_NDTQ010-G1A-AEAT]
U54  SN74LVC2G14DBVR  [SOT23-6]
U107  SN74LVC1G07DCKR  [SC70-5XB]

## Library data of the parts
C806 = CAP_NP: CAP CHIP 1UF 25V(+-10%,X6S,0402); CLASS: DISCRETE; MATERIAL: X6S; Manuf_PN: GRM155C81E105K; Manuf_name: MURATA ERIE N.A. INC TAIWAN BRANCH Okayama Murata Mfg.Co..Ltd.Wakura Murata Mfg.; Manuftr: MUR; Part_Type: *LF_C0402; TOLERANCE: 10%; VOLTAGE: 25V
C975 C1151 = CAP_NP: CAP CHIP 100NF 50V(+-10%,X7R,0402); CLASS: DISCRETE; MATERIAL: X7R; Manuf_PN: CC0402KRX7R9BB104; Manuf_name: YAGEO CORPORATION; Manuftr: YGO; Part_Type: *LF_C0402; TOLERANCE: 10%; VOLTAGE: 50V
C1152 = CAP_NP: CAP CHIP 0.01U 50V(+-10%,X7R,0402); CLASS: DISCRETE; MATERIAL: X7R; Manuf_PN: WBM155R71H103K; Manuf_name: MURATA ERIE N.A. INC TAIWAN BRANCH Okayama Murata Mfg.Co.,Ltd.; Manuftr: MUR; Part_Type: *LF_C0402; TOLERANCE: 10%; VOLTAGE: 50V
C1153 = CAP_NP: CAP CHIP 22U 10V(+-20%,X6S,0805)MUR; CLASS: DISCRETE; MATERIAL: X6S; Manuf_PN: GRM21BC81A226M; Manuf_name: MURATA ERIE N.A. INC TAIWAN BRANCH Okayama Murata Mfg.Co.,Ltd.Wakura Murata Mfg.; Manuftr: MUR; Part_Type: *LF_C0805; TOLERANCE: 20%; VOLTAGE: 10V
C1230 C1231 C1252 = CAP_NP: CAP CHIP 100PF 16V(+-10%,X7R,0201); CLASS: DISCRETE; MATERIAL: X7R; Manuf_PN: GRM033R71C101K; Manuf_name: MURATA ERIE N.A. INC TAIWAN BRANCH Okayama Murata Mfg.Co.,Ltd.Wakura Murata Mfg.; Manuftr: MUR; Part_Type: *LF_C0201; TOLERANCE: 10%; VOLTAGE: 16V
C1232 = CAP_NP: CAP CHIP 100NF 50V(+-10%,X7R,0402); CLASS: DISCRETE; MATERIAL: X7R; Manuf_PN: CC0402KRX7R9BB104; Manuf_name: YAGEO CORPORATION; Manuftr: YGO; Not_insert: NI; Part_Type: *LF_C0402; TOLERANCE: 10%; VOLTAGE: 50V
J41 = SCONN120_6108312150QLF: CONN SMD HEADER 120P 2R MS(P0.8,H5.7); CLASS: IO; ESD_CDM: N/A; ESD_HBM: N/A; ESD_MM: N/A; MATERIAL: IO; MSD: NA; Manuf_PN: 61083-12250QLF; Manuf_name: AMPHENOL EAST ASIA LIMITED (Amphenol-TCS) (Shangh; Manuftr: APL; PIN_LENGTH_LONG_PIN: 32 MILS; PIN_LENGTH_SHORT_PIN: 32 MILS; Part_Type: *LF_Connector
J55 = SCONN5_475900001: CONN SMD MICRO-USB 5P 1R MR(H2.5); CLASS: IO; MATERIAL: IO; Manuf_PN: 47590-0001; Manuf_name: MOLEX TAIWAN LTD.DONGGUAN MOLEX INTERCONNECT CO., LTD; Manuftr: MLX; Part_Type: *LF_Connector
R3043 R3047 R4358 = R: RES CHIP 4.7K 1/16W +-5% (0402); CLASS: DISCRETE; MATERIAL: CHIP; Manuf_PN: RR0510S-472-JN; Manuf_name: CYNTEC CO.. LTD.; Manufacturer: CYN; Manuftr: CYN; Not_insert: NI; Part_Type: *LF_Resistor; TOLERANCE: 5%; WATTAGE: 1/16W
R3044 R3045 = R: RES CHIP 22 1/16W +-1%(0402); BOM: AST2300; CLASS: DISCRETE; MATERIAL: CHIP; Manuf_PN: CR0222R0F002S; Manuf_name: RTECH TECHNOLOGY CO..LTD. (Compostar); Manufacturer: CYN; Manuftr: RHT; Part_Type: *LF_Resistor; TOLERANCE: 1%; WATTAGE: 1/16W
R3048 = R: RES CHIP 100 1/16W +-5% (0402); CLASS: DISCRETE; MATERIAL: CHIP; Manuf_PN: RR0510S-101-JN; Manuf_name: CYNTEC CO.. LTD.; Manuftr: CYN; Part_Type: *LF_Resistor; TOLERANCE: 5%; WATTAGE: 1/16W
R3049 = R: RES CHIP 10K 1/16W 5%(0402); CLASS: DISCRETE; MATERIAL: CHIP; Manuf_PN: RR0510S-103-JN; Manuf_name: CYNTEC CO.. LTD.; Manuftr: CYN; Not_insert: NI; Part_Type: *LF_Resistor; TOLERANCE: 5%; WATTAGE: 1/16W
R3050 R3053 R3054 = R: RES CHIP 33 1/16W +-5% (0402); CLASS: DISCRETE; MATERIAL: CHIP; Manuf_PN: RR0510S-330-JN; Manuf_name: CYNTEC CO.. LTD.; Manuftr: CYN; Part_Type: *LF_Resistor; TOLERANCE: 5%; WATTAGE: 1/16W
R3051 = R: RES CHIP 16K 1/16W +-1%(0402); CLASS: DISCRETE; MATERIAL: CHIP; Manuf_PN: RC0402FR-0716KL; Manuf_name: YAGEO CORPORATION; Manuftr: YGO; Part_Type: *LF_Resistor; TOLERANCE: 1%; WATTAGE: 1/16W
R3052 = R: RES CHIP 4.7K 1/16W +-1%(0402); CLASS: DISCRETE; MATERIAL: CHIP; Manuf_PN: RTT024701FTH; Manuf_name: RALEC ELECTRONIC CO.; Manufacturer: CYN; Manuftr: RLC; Part_Type: *LF_Resistor; TOLERANCE: 1%; WATTAGE: 1/16W
R3055 = R: RES CHIP 4.7K 1/16W +-5% (0402); CLASS: DISCRETE; MATERIAL: CHIP; Manuf_PN: RR0510S-472-JN; Manuf_name: CYNTEC CO.. LTD.; Manufacturer: CYN; Manuftr: CYN; Part_Type: *LF_Resistor; TOLERANCE: 5%; WATTAGE: 1/16W
R3474 R3551 R4356 R4357 = R: RESISTOR CHIP 0 1/16W +-5%(0402); CLASS: DISCRETE; MATERIAL: CHIP; Manuf_PN: RR0510X-000-XN; Manuf_name: CYNTEC CO.. LTD.; Manuftr: CYN; Not_insert: NI; Part_Type: *LF_Resistor; TOLERANCE: 5%; WATTAGE: 1/16W
R3552 R3618 = R: RES CHIP 22 1/16W +-1%(0402); CLASS: DISCRETE; FPLIST: R0402,R0402-0201; MATERIAL: CHIP; Manuf_PN: CR0222R0F002S; Manuf_name: RTECH TECHNOLOGY CO..LTD. (Compostar); Manuftr: RHT; Part_Type: *LF_Resistor; TOLERANCE: 1%; WATTAGE: 1/16W
SW4 = SW4P_PS022N12AAK1: SWITCH PUSH BUTTON(PS022-N12AAK-1); CLASS: IO; DIP_SMD: DIP; ESD_CDM: NA; ESD_HBM: NA; ESD_MM: NA; MATERIAL: MECH; MSD: NA; Manuf_PN: PS022-N12AAK-1; Manuf_name: Well Buying Industrial CO.LTD,; Manuftr: WBI; PIN_LENGTH_LONG_PIN: 115 MILS; PIN_LENGTH_SHORT_PIN: 115 MILS; Part_Type: *LF_Mech
SW6 = SW_PUSHBUTTON4P_NDT010-J1A-AEAT: SWITCH SMD DETECTOR(NDTQ010-G1A-AEAT); CLASS: IO; ESD_CDM: NA; ESD_HBM: NA; ESD_MM: NA; MATERIAL: MECH; MSD: NA; Manuf_PN: NDTQ010-G1A-AEAT; Manuf_name: MISAKI ELECTRONICS CO.,LTD. (Taiwan MASAKI ELECTR; Manuftr: MSK; Not_insert: NI; PIN_LENGTH_LONG_PIN: 28 MILS; PIN_LENGTH_SHORT_PIN: 28 MILS; Part_Type: *LF_Mech
U54 = SN74LVC2G34: IC CTRL(6P) SN74LVC2G14DBVR(SOT-23); CLASS: IC; MATERIAL: IC; Manuf_name: TEXAS INSTRUMENTS SUPPLY CO..; Manuftr: TIC; Part_Type: *LF_Chipset
U107 = SN74LVC1G07: IC OTHER(5P)SN74LVC1G07DCKR(SOT); CLASS: IC; MATERIAL: IC; Manuf_name: TEXAS INSTRUMENTS SUPPLY CO..; Manuftr: TIC; Not_insert: NI; Part_Type: *LF_Chipset

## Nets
GND: C806.2 C975.1 C1151.2 C1152.2 C1153.2 C1230.2 C1231.2 C1232.1 C1252.2 J41.21 J41.22 J41.23 J41.24 J41.25 J41.26 J41.27 J41.29 J41.31 J41.36 J41.38 J41.39 J41.41 J41.44 J41.46 J41.47 J41.49 J41.52 J41.54 J41.55 J41.57 J41.60 J41.62 J41.63 J41.65 J41.68 J41.70 J41.71 J41.73 J41.76 J41.78 J41.79 J41.81 J41.84 J41.86 J41.87 J41.89 J41.92 J41.94 J41.95 J41.97 J41.100 J41.102 J41.103 J41.105 J41.108 J41.110 J41.111 J41.113 J41.116 J41.118 J41.119 J55.5(GND) J55.G1 J55.G2 J55.G3 J55.G4 J55.G5 R3048.2 R3049.1 R3052.2 SW4.1 SW4.2 SW4.3 SW6.2 SW6.3 SW6.4 U54.2(GND) U107.3(GND) ; also on sheet 13 17 18 19 20 21 22 23 24 25 26 27 28 29 30 31 32 33 34 35 36 37 38 39 40 41 42 43 44 45 46 47 48 49 50 52 53 54 55 56 57 58 61 62 63 64 65 66 67
P0V9_CTRL: C1231.1 R3551.2 R3552.2 ; also on sheet 57
P1V8_EN: C1230.1 R3474.2 R3618.2 ; also on sheet 44 58
P3V3_STBY: C975.2 C1151.1 C1152.1 C1153.1 C1232.2 J55.1(VBUS) R3043.1 R3047.1 R3051.1 R3055.1 R4358.1 U54.5(VCC) U107.5(VCC) ; also on sheet 17 18 19 20 22 23 24 25 26 27 28 29 30 31 32 33 34 35 36 37 38 39 40 41 42 43 44 45 46 47 48 49 50 52 53 54 55 56 57 58 61 67
P12V_CONN: J41.2 J41.3 J41.4 J41.5 J41.6 J41.7 J41.8 J41.9 J41.10 J41.11 J41.12 J41.13 J41.14 J41.15 J41.16 J41.17 J41.18 ; also on sheet 13 61
CARD_TYPE_DETECTION: J41.33 R3051.2 R3052.1
CLK_100M_PE_DN: J41.50 ; also on sheet 67
CLK_100M_PE_DP: J41.48 ; also on sheet 67
COM_GP_RX: J41.37 J55.3(D+) ; also on sheet 52
COM_GP_TX: J41.35 J55.2(D-) ; also on sheet 52
FLASHCARD_PRSNT_N: J41.1 R3048.1
FM_POWER_EN: R3053.2 R3552.1 R3618.1 R4357.2 ; also on sheet 38 46
FM_POWER_EN_R: J41.51 R3053.1 R4356.1
FM_POWER_EN_R2: R4357.1 R4358.2 U107.4(Y)
FM_POWER_EN_R3: R4356.2 U107.2(A)
LATCH_DETECT: J41.53 R3054.1
LATCH_DETECT_BUFFER: U54.3(2A) U54.6(1Y)
LATCH_DETECT_R: R3054.2 U54.4(2Y)
LATCH_DETECT_SW: C806.1 R3055.2 SW4.4 SW6.1 U54.1(1A)
P3E_1_PESW_RX0_C_DN: J41.90 ; also on sheet 15
P3E_1_PESW_RX0_C_DP: J41.88 ; also on sheet 15
P3E_1_PESW_RX1_C_DN: J41.98 ; also on sheet 15
P3E_1_PESW_RX1_C_DP: J41.96 ; also on sheet 15
P3E_1_PESW_RX2_C_DN: J41.106 ; also on sheet 15
P3E_1_PESW_RX2_C_DP: J41.104 ; also on sheet 15
P3E_1_PESW_RX3_C_DN: J41.114 ; also on sheet 15
P3E_1_PESW_RX3_C_DP: J41.112 ; also on sheet 15
P3E_1_PESW_TX0_DN: J41.93 ; also on sheet 15
P3E_1_PESW_TX0_DP: J41.91 ; also on sheet 15
P3E_1_PESW_TX1_DN: J41.101 ; also on sheet 15
P3E_1_PESW_TX1_DP: J41.99 ; also on sheet 15
P3E_1_PESW_TX2_DN: J41.109 ; also on sheet 15
P3E_1_PESW_TX2_DP: J41.107 ; also on sheet 15
P3E_1_PESW_TX3_DN: J41.117 ; also on sheet 15
P3E_1_PESW_TX3_DP: J41.115 ; also on sheet 15
P3E_2_PESW_RX0_C_DN: J41.58 ; also on sheet 15
P3E_2_PESW_RX0_C_DP: J41.56 ; also on sheet 15
P3E_2_PESW_RX1_C_DN: J41.66 ; also on sheet 15
P3E_2_PESW_RX1_C_DP: J41.64 ; also on sheet 15
P3E_2_PESW_RX2_C_DN: J41.74 ; also on sheet 15
P3E_2_PESW_RX2_C_DP: J41.72 ; also on sheet 15
P3E_2_PESW_RX3_C_DN: J41.82 ; also on sheet 15
P3E_2_PESW_RX3_C_DP: J41.80 ; also on sheet 15
P3E_2_PESW_TX0_DN: J41.61 ; also on sheet 15
P3E_2_PESW_TX0_DP: J41.59 ; also on sheet 15
P3E_2_PESW_TX1_DN: J41.69 ; also on sheet 15
P3E_2_PESW_TX1_DP: J41.67 ; also on sheet 15
P3E_2_PESW_TX2_DN: J41.77 ; also on sheet 15
P3E_2_PESW_TX2_DP: J41.75 ; also on sheet 15
P3E_2_PESW_TX3_DN: J41.85 ; also on sheet 15
P3E_2_PESW_TX3_DP: J41.83 ; also on sheet 15
PWRGD_P3V3_STBY: R3474.1 R3551.1 ; also on sheet 56
RST_PE_N: R3050.1 ; also on sheet 46 67
RST_PE_N_R1: J41.34 R3049.2 R3050.2
RST_PE_SLOT1_1_RESET_N: J41.40 ; also on sheet 46
SMB_BIC_3V3SB_READY_N: C1252.1 J41.32 ; also on sheet 46
SMB_BMC_3V3SB_CLK: R3044.1 ; also on sheet 46
SMB_BMC_3V3SB_CLK_R1: J41.28 R3043.2 R3044.2
SMB_BMC_3V3SB_DAT: R3045.1 ; also on sheet 46
SMB_BMC_3V3SB_DAT_R1: J41.30 R3045.2 R3047.2

Not connected (* = marked no-connect by the designer): J41 19 20 42 43 45 120; J55 4(ID); U107 1(NC)*

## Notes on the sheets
sheet 1
- GLACIER POINT V2
  Carrier Board
sheet 2
- INDEX
- 1  Cover Page
  2  Page Index
  3  Block Diagram
  4  PCIe Topology
  5  Block Diagram ¡V SMBus
  6  Power Sequence
  7  Power Distribution
  8  Block Diagram ¡V Clock
  9  Block Diagram ¡V Reset
  10 Block Diagram ¡V UART&JTAG
  11 BLANK
  12 MEZZ CONN PRIMARY
  13 MEZZ CONN EXTENSION
  14 PCIE SWITCH (STACK1-2)
  15 PCIE SWITCH (STACK3-4)
  16 PCIE SWITCH (STACK5)
  17 PCIE SWITCH (CLOCKS/RESET)
  18 PCIE SWITCH (GPIO)
  19 PCIE SWITCH (PWR1/VSS1)
  20 PCIE SWITCH (PWR2/VSS2)
  21 PCIE SWITCH (PWR3/VSS3)
  22 SPI FLASH/EEPROM/JTAG
  23 PCIE SWITCH UART
  24 100MHz CLOCK GEN
  25 CLOCK BUFFER 1
  26 CLOCK BUFFER 2
  27 LEVEL SHIFTER 1
  28 LEVEL SHIFTER 2
  29 M.2 A
  30 M.2 B
  31 M.2 C
  32 M.2 D
  33 M.2 E
  34 M.2 F
  35 M.2 G
  36 M.2 H
  37 M.2 I
  38 M.2 J
  39 M.2 K
  40 M.2 L
- 41 INA230 / I2C MUX 7
  42 I2C MUX 1-3
  43 I2C MUX 4-6
  44 P3V3 M.2 POWER Switch 1
  45 P3V3 M.2 POWER Switch 2
  46 P3V3 M.2 POWER Switch 3
  47 P3V3 M.2 POWER Switch 4
  48 LED
  49 I2C GPIO
  50 Level Shifter 3
  51 Temperature Sensors/FRU
  52 BIC_SNOWLAKE 1
  53 BIC_SNOWLAKE 2
  54 BIC_SNOWLAKE 3
  55 Level Shifter 4
  56 BIC-VOLTAGE MONITOR
  57 CPLD 1
  58 CPLD 2
  59 CPLD 3
  60 MISC 1
  61 MISC 2
  62 P3V3_STBY
  63 P0V92
  64 P1V8
  65 Mechanical/Delta-L
  66 TDR
  67 DUMMY SYMBOL
- Page Index
sheet 3
- Block Diagram
sheet 4
- PCIe Topology
sheet 5
- Block Diagram - SMBus
sheet 6
- Power Sequence
sheet 7
- Power Distribution
sheet 8
- Block Diagram - Clock
sheet 9
- Block Diagram - Reset
sheet 10
- Block Diagram - JTAG & UART
sheet 11
- BLANK
sheet 12
- SMBus and power enable connection to VR
- CAD Note:
  C1230 place at near location(778.64 648.53)
  C1231 place at near location(7759.90 1327.90)
- Reserve buffer for FM_POWER_EN
- Note: Add UART signal
  -- COM_GP_TX/RX
- R1
- Note: Board voltage level
  3.3V* R2/(R1+R2)= 0.749V = GPV2
- R2
- CAD Note:
  C1252 place near test point(1041.00 133.00)
  at bottom side
- Note: Reserved SW6
  for co-layour purpose
- Micro USB
- MEZZ CONN PRIMARY
